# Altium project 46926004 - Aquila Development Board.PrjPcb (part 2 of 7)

## Sheet 210_Translators.SchDoc: Aquila Development Board
size Letter; Organization: Linear Computing Inc.; Address1: 6415 Northwest Drive; Address2: Mississauga, ON, L4V1X1; Address3: Canada; SheetNumber: 8; SheetTotal: 34
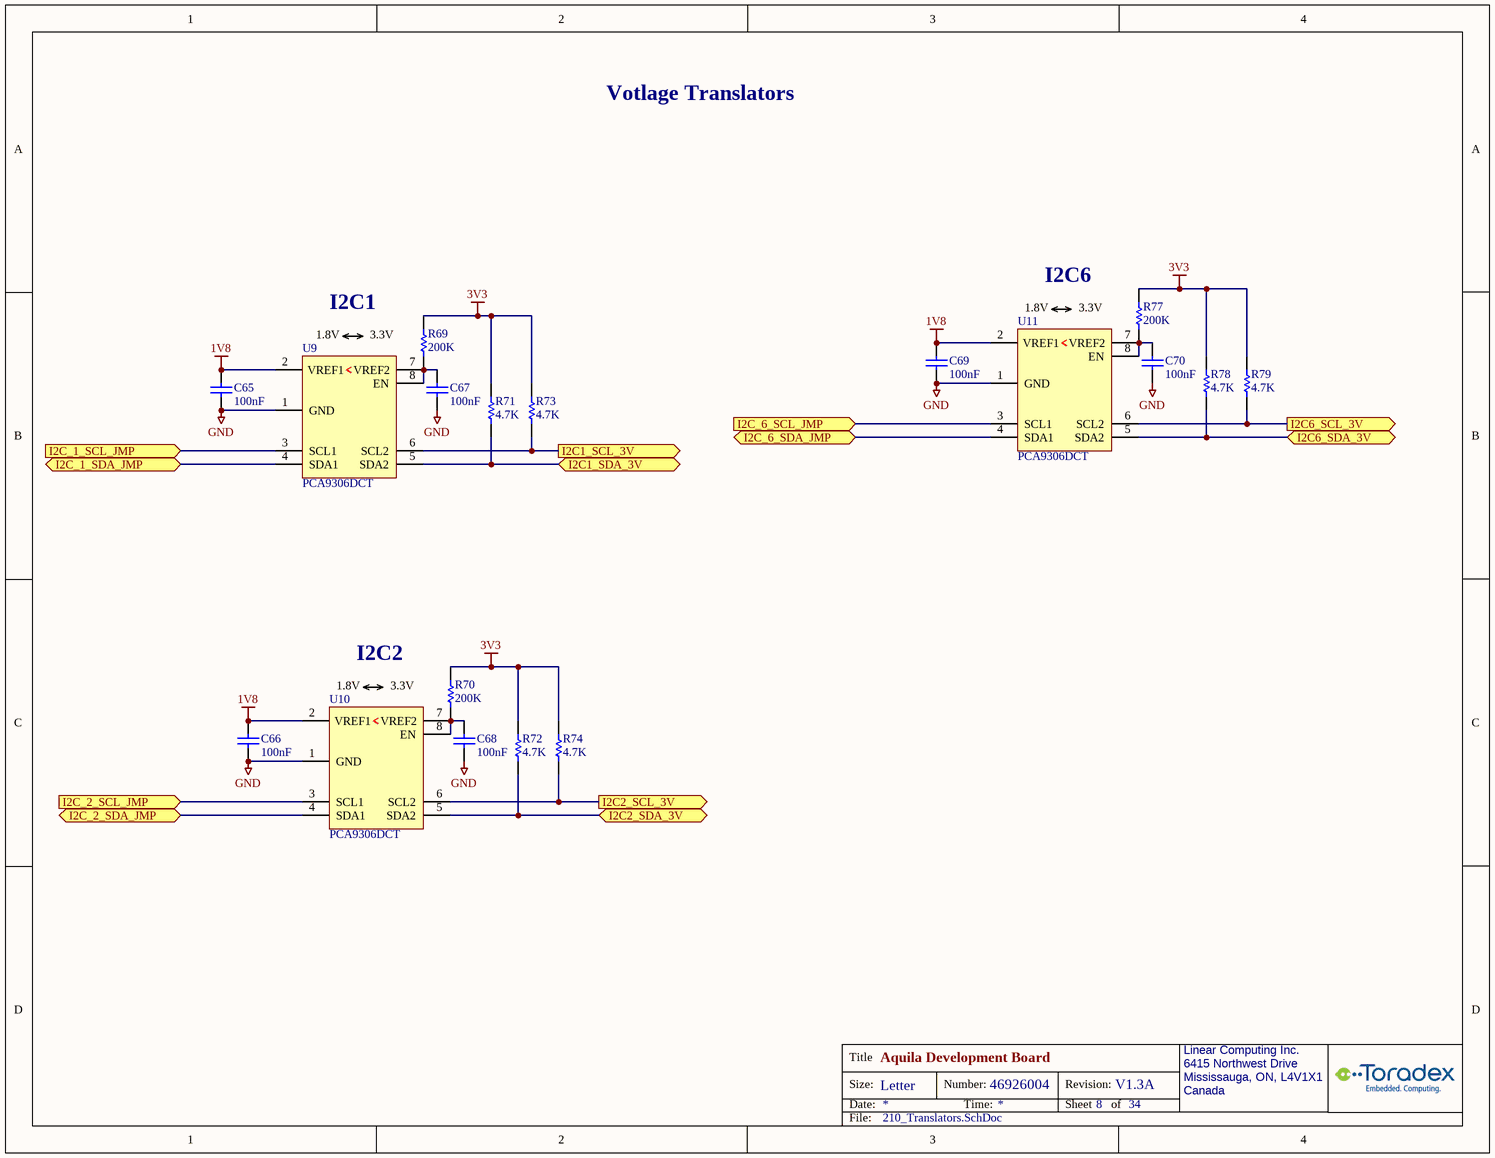
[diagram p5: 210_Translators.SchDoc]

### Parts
C65  100nF  [C0402_CAPC1005L]
C66  100nF  [C0402_CAPC1005L]
C67  100nF  [C0402_CAPC1005L]
C68  100nF  [C0402_CAPC1005L]
C69  100nF  [C0402_CAPC1005L]
C70  100nF  [C0402_CAPC1005L]
R69  value 200K  [R0402_RESC1005L]  (hidden comment: 1540-Res-0402-200k)
R70  value 200K  [R0402_RESC1005L]  (hidden comment: 1540-Res-0402-200k)
R71  value 4.7K  [R0402_RESC1005L]  (hidden comment: 2233-Res-0402-4.7K)
R72  value 4.7K  [R0402_RESC1005L]  (hidden comment: 2233-Res-0402-4.7K)
R73  value 4.7K  [R0402_RESC1005L]  (hidden comment: 2233-Res-0402-4.7K)
R74  value 4.7K  [R0402_RESC1005L]  (hidden comment: 2233-Res-0402-4.7K)
R77  value 200K  [R0402_RESC1005L]  (hidden comment: 1540-Res-0402-200k)
R78  value 4.7K  [R0402_RESC1005L]  (hidden comment: 2233-Res-0402-4.7K)
R79  value 4.7K  [R0402_RESC1005L]  (hidden comment: 2233-Res-0402-4.7K)
U9  PCA9306DCT  [TSSO3x5-G8/X.35]
U10  PCA9306DCT  [TSSO3x5-G8/X.35]
U11  PCA9306DCT  [TSSO3x5-G8/X.35]

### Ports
I2C1_SCL_3V (out), I2C1_SDA_3V (bidir), I2C2_SCL_3V (out), I2C2_SDA_3V (bidir), I2C6_SCL_3V (out), I2C6_SDA_3V (bidir), I2C_1_SCL_JMP (in), I2C_1_SDA_JMP (bidir), I2C_2_SCL_JMP (in), I2C_2_SDA_JMP (bidir), I2C_6_SCL_JMP (in), I2C_6_SDA_JMP (bidir)

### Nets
1V8: C65.2 C66.2 C69.2 U9.2(VREF1) U10.2(VREF1) U11.2(VREF1)
3V3: R69.1 R70.1 R71.1 R72.1 R73.1 R74.1 R77.1 R78.1 R79.1
GND: C65.1 C66.1 C67.1 C68.1 C69.1 C70.1 U9.1(GND) U10.1(GND) U11.1(GND)
I2C1_SCL_3V: R73.2 U9.6(SCL2) ; port I2C1_SCL_3V
I2C1_SDA_3V: R71.2 U9.5(SDA2) ; port I2C1_SDA_3V
I2C2_SCL_3V: R74.2 U10.6(SCL2) ; port I2C2_SCL_3V
I2C2_SDA_3V: R72.2 U10.5(SDA2) ; port I2C2_SDA_3V
I2C6_SCL_3V: R79.2 U11.6(SCL2) ; port I2C6_SCL_3V
I2C6_SDA_3V: R78.2 U11.5(SDA2) ; port I2C6_SDA_3V
I2C_1_SCL_JMP: U9.3(SCL1) ; port I2C_1_SCL_JMP
I2C_1_SDA_JMP: U9.4(SDA1) ; port I2C_1_SDA_JMP
I2C_2_SCL_JMP: U10.3(SCL1) ; port I2C_2_SCL_JMP
I2C_2_SDA_JMP: U10.4(SDA1) ; port I2C_2_SDA_JMP
I2C_6_SCL_JMP: U11.3(SCL1) ; port I2C_6_SCL_JMP
I2C_6_SDA_JMP: U11.4(SDA1) ; port I2C_6_SDA_JMP
NetC67_2: C67.2 R69.2 U9.7(VREF2) U9.8(EN)
NetC68_2: C68.2 R70.2 U10.7(VREF2) U10.8(EN)
NetC70_2: C70.2 R77.2 U11.7(VREF2) U11.8(EN)

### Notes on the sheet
- Votlage Translators
- I2C6
- (near U9) 1.8V
- I2C1
- 3.3V
- (near U11) 1.8V
- (near U10) 1.8V
- I2C2

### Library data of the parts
C65-C70 = 1566-Cap-0402-100nF/50V: (-55 to 125 DegC AEC) Cap Ceramic 0.1uF 50V X7R 10% 0402; MfrNo: GRT155R71H104KE01D; Mfr: Murata; Alt: CL05B104KB54PNC,GCM155R71H104ME02D,GCM155R71H104KE02D,GCM155R71H104KE02J; PN: 1566
R69 R70 R77 = 1540-Res-0402-200k: (-55 to 155 DegC AEC) RES 200K OHM 1% 1/16W 100ppm 0402; Mfr: Stackpole Electronics; MfrNo: RMCF0402FT200K; Alt: AC0402FR-07200KL,AC0402FR-7W200KL,ERJ-2RKF2003X; PN: 1540
R71-R74 R78 R79 = 2233-Res-0402-4.7K: (-55 to 155 DegC) RES 4.70K OHM 1/16W 1% 0402 100ppm; MfrNo: RC0402FR-074K7L; Mfr: Yageo; PN: 2233
U9-U11 = 0972-PCA9306DCT: (-40 to 85 DegC) IC TRANSLTR BIDIRECTIONAL I2C SM8; MfrNo: PCA9306DCTR; Mfr: Texas Instruments; PN: 972

## Sheet 220_Debug.SchDoc: Aquila Development Board
size Letter; Organization: Toradex Solutions Inc.; Address1: 6415 Northwest Drive; Address2: Mississauga, ON, L4V 1X1; Address3: Canada; SheetNumber: 10; SheetTotal: 34
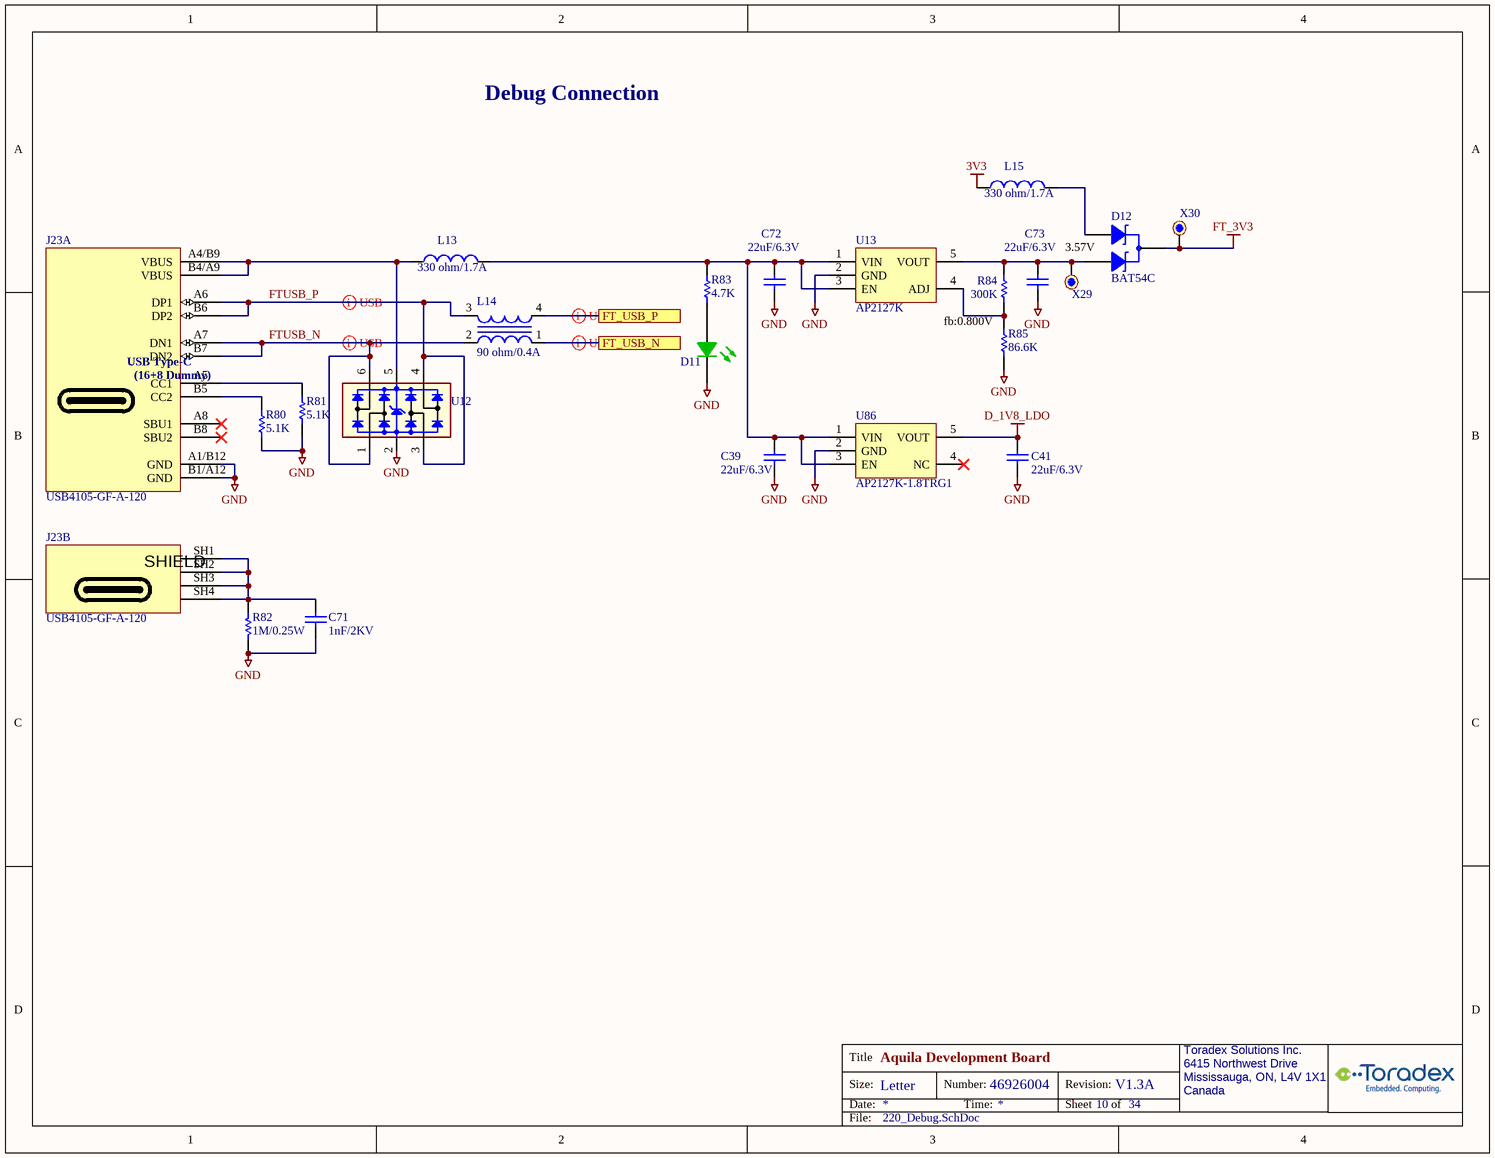
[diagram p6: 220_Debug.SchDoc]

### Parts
C39  22uF/6.3V  [C0402_CAPC1005L]
C41  22uF/6.3V  [C0402_CAPC1005L]
C71  value 1nF/2KV  [C/1206]  (hidden comment: 0567-Cap-1206-1nF/2KV)
C72  22uF/6.3V  [C0402_CAPC1005L]
C73  22uF/6.3V  [C0402_CAPC1005L]
D11  Status  [LED-SMT-0603_APT1608CGCK]  (value not drawn)
D12  BAT54C  [SOT23_M]
J23  USB4105-GF-A-120  [GCT_USB4105GFA120]  (parts A,B of 2)
L13  value 330 ohm/1.7A  [C/0603]  (hidden comment: 0405-Fer-0603-330ohm/1.7A)
L14  90 ohm/0.4A  [COMMON_CHOKE_BOURNS_SRF2012-900YA]
L15  value 330 ohm/1.7A  [C/0603]  (hidden comment: 0405-Fer-0603-330ohm/1.7A)
R80  value 5.1K  [R/0603]  (hidden comment: 0227-Res-0603-5.1K)
R81  value 5.1K  [R/0603]  (hidden comment: 0227-Res-0603-5.1K)
R82  value 1M/0.25W  [R/1206]  (hidden comment: 1860-Res-1206-1M-5%-0.25W)
R83  value 4.7K  [R0402_RESC1005L]  (hidden comment: 2233-Res-0402-4.7K)
R84  value 300K  [R/0603]  (hidden comment: 0176-Res-0603-300K)
R85  value 86.6K  [R0402_RESC1005L]  (hidden comment: 1539-Res-0402-86.6k)
U12  TPD4E001  [SOT23-6]  (value not drawn)
U13  AP2127K  [SOT23-5AN]
U86  AP2127K-1.8TRG1  [SOT23-5AN]
X29  000-TestPoint  [TestPoint_1]  (value not drawn)
X30  000-TestPoint  [TestPoint_1]  (value not drawn)

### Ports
FT_USB_N, FT_USB_P

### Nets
3V3: L15.1
D_1V8_LDO: C41.1 U86.5(VOUT)
FT_3V3: D12.3(K) X30.1
GND: C39.2 C41.2 C71.1 C72.2 C73.2 D11.2(K) J23.A1/B12(GND) J23.B1/A12(GND) R80.2 R81.2 R82.2 R85.1 U12.2 U13.2(GND) U86.2(GND)
FT_USB_N: L14.1 ; port FT_USB_N
FT_USB_P: L14.4 ; port FT_USB_P
FTUSB_N: J23.A7(DN1) J23.B7(DN2) L14.2 U12.1 U12.6
FTUSB_P: J23.A6(DP1) J23.B6(DP2) L14.3 U12.3 U12.4
NetC39_1: C39.1 C72.1 L13.2 R83.2 U13.1(VIN) U13.3(EN) U86.1(VIN) U86.3(EN)
NetC71_2: C71.2 J23.SH1(SHIELD) J23.SH2(SHIELD) J23.SH3(SHIELD) J23.SH4(SHIELD) R82.1
NetC73_1: C73.1 D12.2(A2) R84.1 U13.5(VOUT) X29.1
NetD11_1: D11.1(A) R83.1
NetD12_1: D12.1(A1) L15.2
NetJ23_A4/B9: J23.A4/B9(VBUS) J23.B4/A9(VBUS) L13.1 U12.5
NetJ23_A5: J23.A5(CC1) R81.1
NetJ23_B5: J23.B5(CC2) R80.1
NetR84_2: R84.2 R85.2 U13.4(ADJ)

Not connected (* = marked no-connect by the designer): J23 A8(SBU1)* B8(SBU2)*; U86 4(NC)*

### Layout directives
differential pair; differential pair class USB_FT: FT_USB_N, FT_USB_P
differential pair; differential pair class USB_FT_CON: FTUSB_N, FTUSB_P

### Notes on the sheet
- Debug Connection
- 3.57V
- (near R85) fb:0.800V

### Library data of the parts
C39 C41 C72 C73 = 2404-Cap-0402-22uF/6.3V: (-55 to 85 DegC) CAP CER 22UF 6.3V 20% X5R 0402; MfrNo: GRM155R60J226ME11D; Mfr: Murata; PN: 2404
C71 = 0567-Cap-1206-1nF/2KV: (-55 to 125 DegC) CAP CER 1000PF 2KV X7R 1206; Mfr: Johanson Dielectrics Inc.; MfrNo: 202R18W102KV4E; PN: 567; Alt: 478-2956-1-ND; Alt2: 399-4819-1-ND
D11 = 0333-LED Green 0603: (-40 to 85 DegC) LED GREEN 0603 50mcd; MfrNo: APT1608CGCK; Mfr: Kingbright; Alt: 754-1357-1-ND; Alt2: 160-1834-1-ND; PN: 333; DR: 754-1116-6-ND; DR2: 604-APT1608CGCK
D12 = 0242B-BAT54C: (-55 to 125 DegC) DIODE SCHOTTKY 30V 200MA SOT23, comm. Cathode; Mfr: ON Semi; MfrNo: BAT54CLT1G; Alt: BAT54CFSCT-ND; Alt2: BAT54C-FDICT-ND; PN: 242; TR: BAT54CLT1GOSTR-ND; DR: BAT54CLT1GOSDKR-ND; DR2: 863-BAT54CLT1G
J23 = 1660-Conn-USB-Type-C: (-40 to 85 DegC) Conn USB TYPE C RA, 24 (16+8 Dummy) Position, SMT/TH; Mfr: Global Connector Technology; Desc: (-40 to 85 DegC) Conn USB TYPE C RA SMT/TH; PN: 1660
L13 L15 = 0405-Fer-0603-330ohm/1.7A: (-55 to 125 DegC) FERRITE BEAD 330 OHM 0603 1.7A 80mohm, typ 48mohm; Mfr: TDK Corporation; MfrNo: MPZ1608S331ATA00; PN: 405; TR: 445-5221-2-ND; DR: 445-5221-6-ND; DR2: 810-MPZ1608S331ATA00
L14 = 0277-Ind-2x1.2-90ohm/0.4A-Choke: (-40 to 125 DegC) INDUCTOR COMMON MODE 90 OHM 0.4A 0.3ohm; MfrNo: SRF2012-900YA; Mfr: Bourns Inc.; PN: 277; Alt: 445-2207-1-ND
R80 R81 = 0227-Res-0603-5.1K: (-55 to 155 DegC) RES 5.1K OHM 1/10W 1% 0603 SMD; Mfr: Rohm; MfrNo: MCR03ERTF5101; Alt: 1276-4713-1-ND; Alt2: 311-5.10KHRCT-ND; PN: 227
R82 = 1860-Res-1206-1M-5%-0.25W: (-55 to 155 DegC) RES SMD 1M OHM 5% 0.25W 10ppm 1206; Mfr: TE Connectivity; MfrNo: CRGCQ1206J1M0; PN: 1860; Alt: RMCF1206JT1M00, RMCF1206JG1M00, CR1206-JW-105ELF
R83 = 2233-Res-0402-4.7K: as R71-R74 on sheet 210_Translators
R84 = 0176-Res-0603-300K: (-55 to 155 DegC) RES 300K OHM 1/10W 1% 0603 SMD; Mfr: Yageo; MfrNo: RC0603FR-07300KL; Alt: RHM300KCFCT-ND; PN: 176; Alt2: P300KHCT-ND; TR: 311-300KHRTR-ND
R85 = 1539-Res-0402-86.6k: (-55 to 155 DegC AEC) RES 86.6K OHM 1% 1/16W 100ppm 0402; Mfr: Stackpole Electronics; MfrNo: RMCF0402FT86K6; Alt: AC0402FR-0786K6L,RK73H1ETTP8662F,ERJ-2RKF8662X; PN: 1539
U12 = 0740-TPD4E001: (-40 to 125 DegC AEC) TVS DIODE 5.5VWM 16VC SOT-23-6; MfrNo: TPD4E001QDBVRQ1; Mfr: Texas Instruments; PN: 740; Alt: TPD4E001DBVR
U13 = 0968-AP2127K: (-40 to 85 DegC) IC REG LIN LDO POS ADJ 300MA (450 max) SOT23-5 2.5-6 Vin 0.3Vd@0.3A; Mfr: Diodes Incorporated; MfrNo: AP2127K-ADJTRG1; PN: 968
U86 = 2737-AP2127K-1.8TRG1: (-40 to 85 DegC) IC REG LIN LDO POS 1.8V 300MA (450 max) SOT23-5 2.5-6 Vin 0.3Vd@0.3A; Mfr: Diodes; PN: 2737
X29 X30 = 000-TestPoint: TestPoint TH; Note: this is PCB footprint only, no parts to buy or assemble

## Sheet 300_USB1_OTG.SchDoc: Aquila Development Board
size A3; Organization: Toradex Solutions Inc.; Address1: 6415 Northwest Drive; Address2: Mississauga, ON, L4V 1X1; Address3: Canada; SheetNumber: 14; SheetTotal: 34
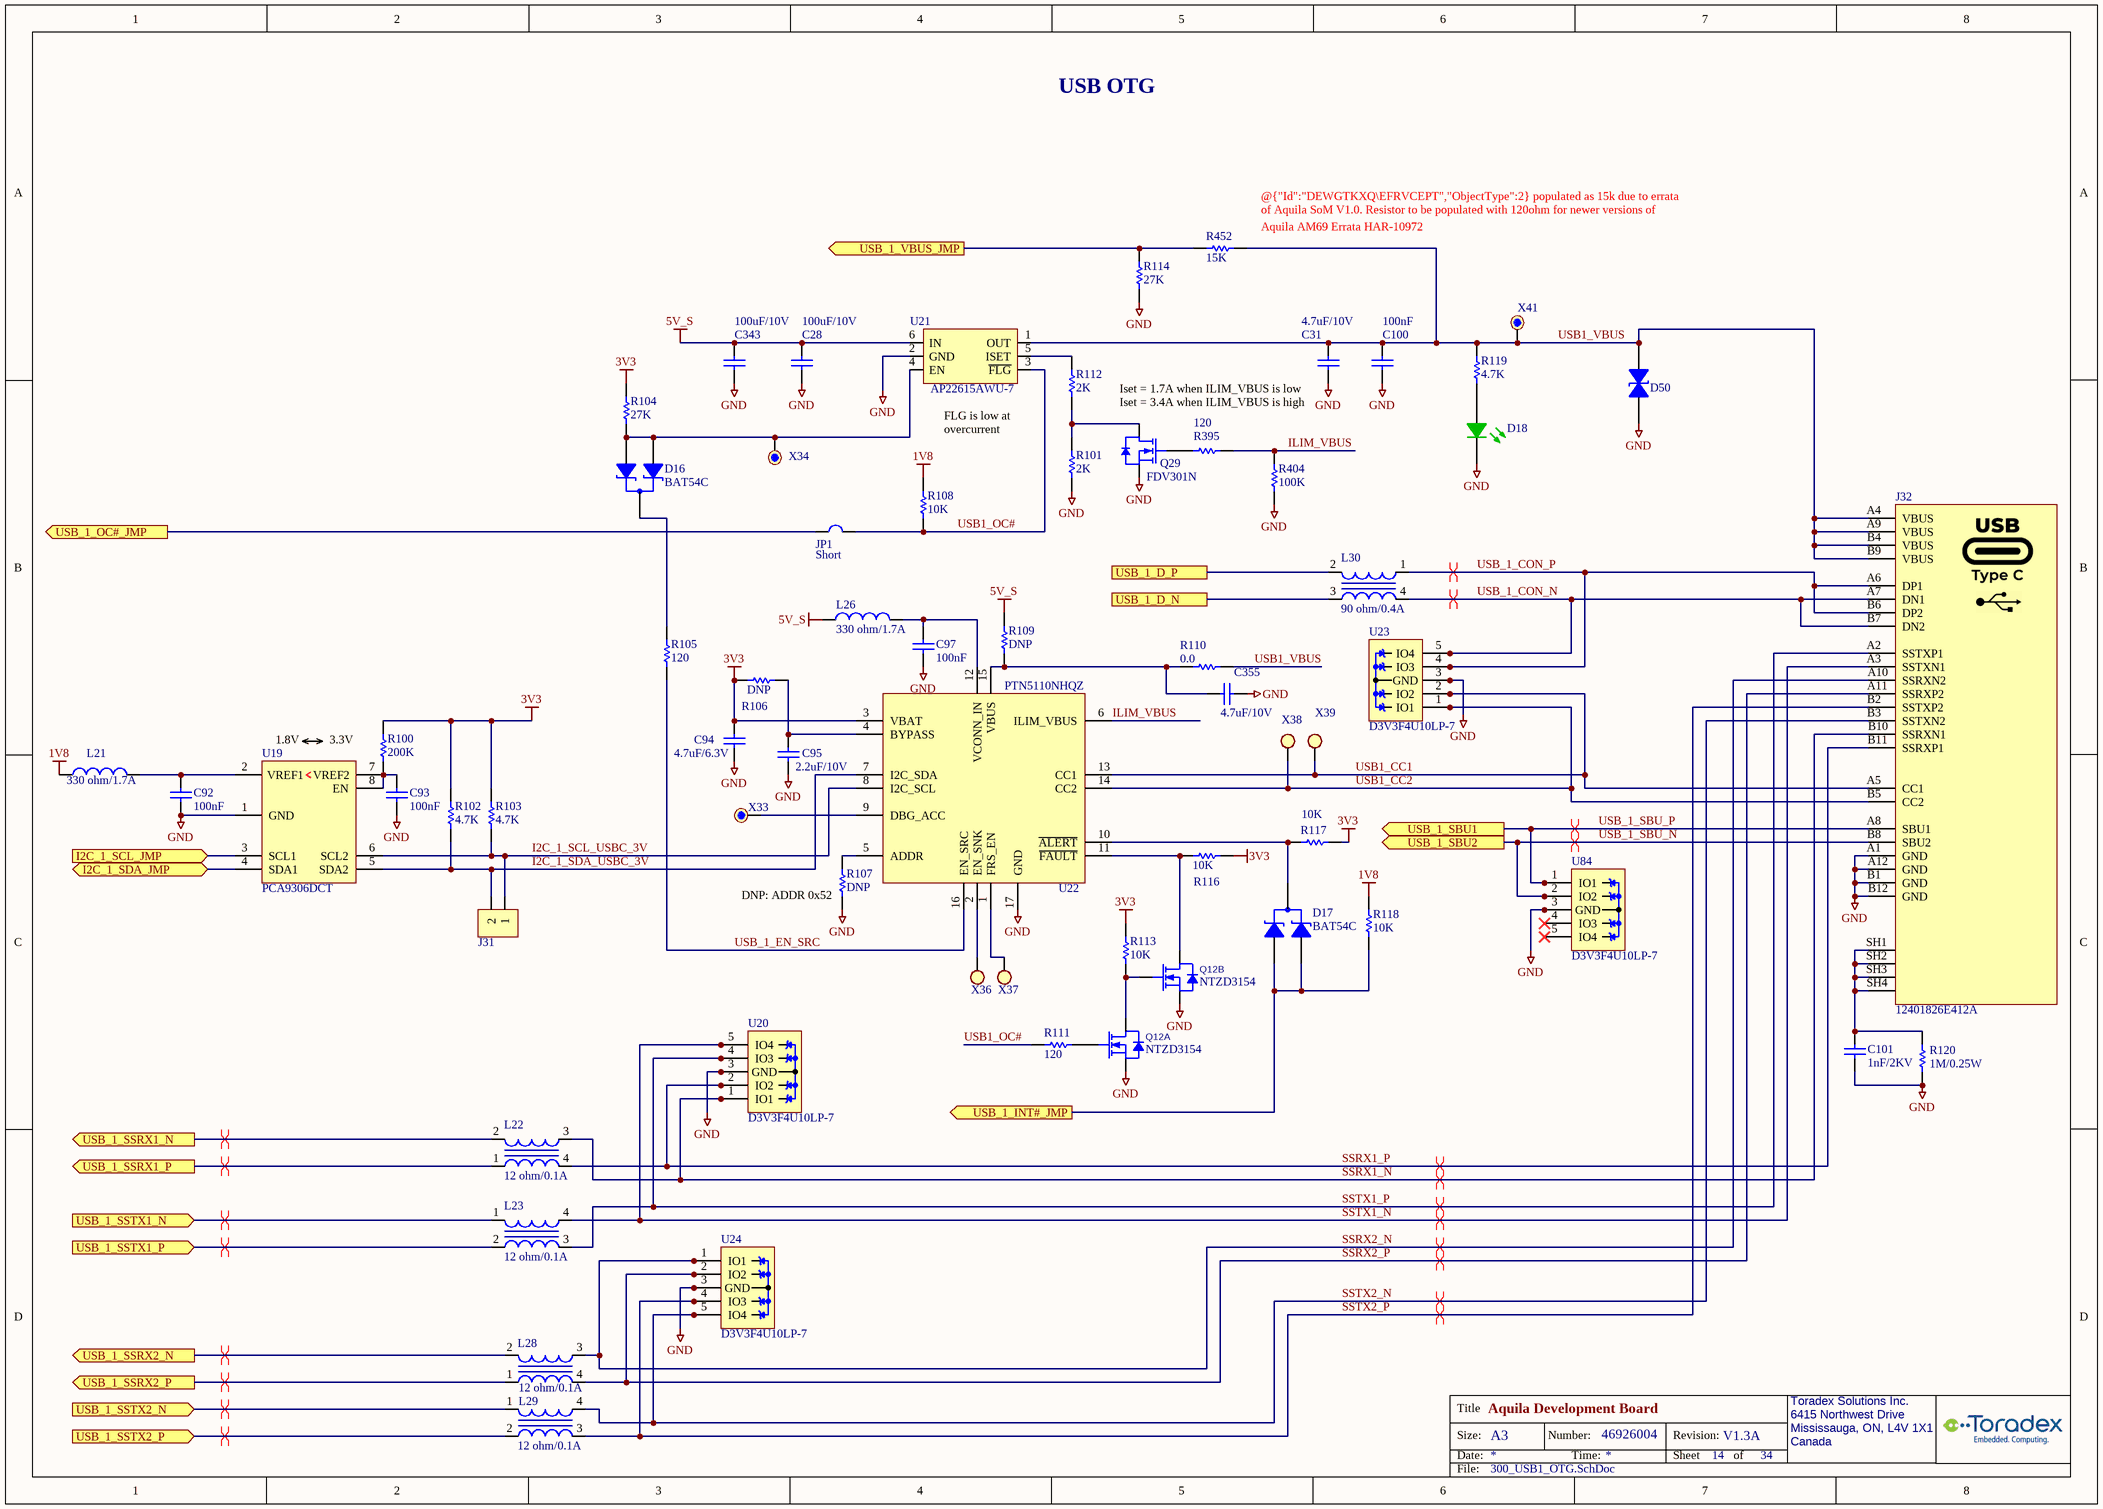
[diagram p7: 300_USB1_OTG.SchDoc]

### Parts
C28  100uF/10V  [C/1206]
C31  value 4.7uF/10V  [C/0603]  (hidden comment: 2093-Cap-0603-4.7uF/10V)
C92  100nF  [C0402_CAPC1005L]
C93  100nF  [C0402_CAPC1005L]
C94  value 4.7uF/6.3V  [C0402_CAPC1005L]  (hidden comment: 0354-Cap-0402-4.7uF/6.3V)
C95  value 2.2uF/10V  [C0402_CAPC1005L]  (hidden comment: 2234-Cap-0402-2.2uF/10V)
C97  100nF  [C0402_CAPC1005L]
C100  100nF  [C0402_CAPC1005L]
C101  value 1nF/2KV  [C/1206]  (hidden comment: 0567-Cap-1206-1nF/2KV)
C343  100uF/10V  [C/1206]
C355  value 4.7uF/10V  [C/0603]  (hidden comment: 2093-Cap-0603-4.7uF/10V)
D16  BAT54C  [SOT23_M]
D17  BAT54C  [SOT23_M]
D18  Status  [LED-SMT-0603_APT1608CGCK]  (value not drawn)
D50  D5V0L1B2S9-7  [SOD923_DIO]  (value not drawn)
J31  000-Hdr-2pin  [HDR1X2]  (value not drawn)  (no BOM)
J32  12401826E412A  [AMPHENOL_12401826E412A]
JP1  Short  [Short_040]  (net tie, no BOM)
L21  value 330 ohm/1.7A  [C/0603]  (hidden comment: 0405-Fer-0603-330ohm/1.7A)
L22  12 ohm/0.1A  [COIL0302]
L23  12 ohm/0.1A  [COIL0302]
L26  value 330 ohm/1.7A  [C/0603]  (hidden comment: 0405-Fer-0603-330ohm/1.7A)
L28  12 ohm/0.1A  [COIL0302]
L29  12 ohm/0.1A  [COIL0302]
L30  90 ohm/0.4A  [COMMON_CHOKE_BOURNS_SRF2012-900YA]
Q12  NTZD3154  [SOT563]  (parts A,B of 2)
Q29  FDV301N  [SOT23]
R100  value 200K  [R0402_RESC1005L]  (hidden comment: 1540-Res-0402-200k)
R101  value 2K  [R/0603]  (hidden comment: 1758-Res-0603-2K)
R102  value 4.7K  [R0402_RESC1005L]  (hidden comment: 2233-Res-0402-4.7K)
R103  value 4.7K  [R0402_RESC1005L]  (hidden comment: 2233-Res-0402-4.7K)
R104  value 27K  [R0402_RESC1005L]  (hidden comment: 1538-Res-0402-27k)
R105  value 120  [R0402_RESC1005L]  (hidden comment: 1552-Res-0402-120)
R106  value DNP  [R/0603]  (hidden comment: 0000-Res-0603-DNP)
R107  value DNP  [R/0603]  (hidden comment: 0000-Res-0603-DNP)
R108  value 10K  [R0402_RESC1005L]  (hidden comment: 1572-Res-0402-10K)
R109  value DNP  [R/0603]  (hidden comment: 0000-Res-0603-DNP)
R110  value 0.0  [R/0603]  (hidden comment: 0195-Res-0603-0.0ohm)
R111  value 120  [R0402_RESC1005L]  (hidden comment: 1552-Res-0402-120)
R112  value 2K  [R/0603]  (hidden comment: 1758-Res-0603-2K)
R113  value 10K  [R0402_RESC1005L]  (hidden comment: 1572-Res-0402-10K)
R114  value 27K  [R0402_RESC1005L]  (hidden comment: 1538-Res-0402-27k)
R116  value 10K  [R0402_RESC1005L]  (hidden comment: 1572-Res-0402-10K)
R117  value 10K  [R0402_RESC1005L]  (hidden comment: 1572-Res-0402-10K)
R118  value 10K  [R0402_RESC1005L]  (hidden comment: 1572-Res-0402-10K)
R119  value 4.7K  [R0402_RESC1005L]  (hidden comment: 2233-Res-0402-4.7K)
R120  value 1M/0.25W  [R/1206]  (hidden comment: 1860-Res-1206-1M-5%-0.25W)
R395  value 120  [R0402_RESC1005L]  (hidden comment: 1552-Res-0402-120)
R404  value 100K  [R0402_RESC1005L]  (hidden comment: 1977-Res-0402-100K)
R452  value 15K  [R0402_RESC1005L]  (hidden comment: 1550-Res-0402-15K)
U19  PCA9306DCT  [TSSO3x5-G8/X.35]
U20  D3V3F4U10LP-7  [10-UFDFN]
U21  AP22615AWU-7  [TSOT26]
U22  PTN5110NHQZ  [QFN40P260X260X40-17N-D]
U23  D3V3F4U10LP-7  [10-UFDFN]
U24  D3V3F4U10LP-7  [10-UFDFN]
U84  D3V3F4U10LP-7  [10-UFDFN]
X33  000-TestPoint  [TestPoint_1]  (value not drawn)
X34  000-TestPoint  [TestPoint_1]  (value not drawn)
X36  000-TestPoint2  [TestPoint_3]  (value not drawn)
X37  000-TestPoint2  [TestPoint_3]  (value not drawn)
X38  000-TestPoint2  [TestPoint_3]  (value not drawn)
X39  000-TestPoint2  [TestPoint_3]  (value not drawn)
X41  000-TestPoint  [TestPoint_1]  (value not drawn)

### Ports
I2C_1_SCL_JMP (in), I2C_1_SDA_JMP (bidir), USB_1_D_N, USB_1_D_P, USB_1_INT#_JMP (out), USB_1_OC#_JMP (out), USB_1_SBU1 (out), USB_1_SBU2 (out), USB_1_SSRX1_N (out), USB_1_SSRX1_P (out), USB_1_SSRX2_N (out), USB_1_SSRX2_P (out), USB_1_SSTX1_N (in), USB_1_SSTX1_P (in), USB_1_SSTX2_N (in), USB_1_SSTX2_P (in), USB_1_VBUS_JMP (out)

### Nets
1V8: L21.1 R108.1 R118.1
3V3: C94.2 R100.1 R102.1 R103.1 R104.2 R106.1 R113.1 R116.1 R117.1 U22.3(VBAT)
5V_S: C28.2 C343.2 L26.1 R109.2 U21.6(IN)
GND: C28.1 C31.1 C92.1 C93.1 C94.1 C95.1 C97.1 C100.1 C101.1 C343.1 C355.1 D18.2(K) D50.1 J32.A1(GND) J32.A12(GND) J32.B1(GND) J32.B12(GND) Q12.1(S) Q12.4(S) Q29.2(S) R101.2 R107.1 R114.1 R120.2 R404.1 U19.1(GND) U20.3(GND) U20.8(GND) U21.2(GND) U22.17(GND) U23.3(GND) U23.8(GND) U24.3(GND) U24.8(GND) U84.3(GND) U84.8(GND)
I2C_1_SCL_JMP: U19.3(SCL1) ; port I2C_1_SCL_JMP
I2C_1_SCL_USBC_3V: J31.1 R103.2 U19.6(SCL2) U22.8(I2C_SCL)
I2C_1_SDA_JMP: U19.4(SDA1) ; port I2C_1_SDA_JMP
I2C_1_SDA_USBC_3V: J31.2 R102.2 U19.5(SDA2) U22.7(I2C_SDA)
ILIM_VBUS: R395.1 R404.2 U22.6(ILIM_VBUS)
SSRX1_N: J32.B10(SSRXN1) L22.3 U20.1(IO1) U20.10(NC)
SSRX1_P: J32.B11(SSRXP1) L22.4 U20.2(IO2) U20.9(NC)
SSRX2_N: J32.A10(SSRXN2) L28.3 U24.1(IO1) U24.10(NC)
SSRX2_P: J32.A11(SSRXP2) L28.4 U24.2(IO2) U24.9(NC)
SSTX1_N: J32.A3(SSTXN1) L23.4 U20.5(IO4) U20.6(NC)
SSTX1_P: J32.A2(SSTXP1) L23.3 U20.4(IO3) U20.7(NC)
SSTX2_N: J32.B3(SSTXN2) L29.4 U24.5(IO4) U24.6(NC)
SSTX2_P: J32.B2(SSTXP2) L29.3 U24.4(IO3) U24.7(NC)
USB1_CC1: J32.A5(CC1) U22.13(CC1) U23.2(IO2) U23.9(NC) X39.1
USB1_CC2: J32.B5(CC2) U22.14(CC2) U23.1(IO1) U23.10(NC) X38.1
USB1_OC#: JP1.2(C2) R108.2 R111.2 U21.3(~{FLG})
USB1_VBUS: C31.2 C100.2 D50.2 J32.A4(VBUS) J32.A9(VBUS) J32.B4(VBUS) J32.B9(VBUS) R110.2 R119.2 R452.1 U21.1(OUT) X41.1
USB_1_CON_N: J32.A7(DN1) J32.B7(DN2) L30.4 U23.5(IO4) U23.6(NC)
USB_1_CON_P: J32.A6(DP1) J32.B6(DP2) L30.1 U23.4(IO3) U23.7(NC)
USB_1_D_N: L30.3 ; port USB_1_D_N
USB_1_D_P: L30.2 ; port USB_1_D_P
USB_1_EN_SRC: R105.2 U22.16(EN_SRC)
USB_1_INT#_JMP: D17.1(A1) D17.2(A2) R118.2 ; port USB_1_INT#_JMP
USB_1_OC#_JMP: JP1.1(C1) ; port USB_1_OC#_JMP
USB_1_SBU_N: J32.B8(SBU2) U84.2(IO2) U84.9(NC) ; port USB_1_SBU2
USB_1_SBU_P: J32.A8(SBU1) U84.1(IO1) U84.10(NC) ; port USB_1_SBU1
USB_1_SSRX1_N: L22.2 ; port USB_1_SSRX1_N
USB_1_SSRX1_P: L22.1 ; port USB_1_SSRX1_P
USB_1_SSRX2_N: L28.2 ; port USB_1_SSRX2_N
USB_1_SSRX2_P: L28.1 ; port USB_1_SSRX2_P
USB_1_SSTX1_N: L23.1 ; port USB_1_SSTX1_N
USB_1_SSTX1_P: L23.2 ; port USB_1_SSTX1_P
USB_1_SSTX2_N: L29.1 ; port USB_1_SSTX2_N
USB_1_SSTX2_P: L29.2 ; port USB_1_SSTX2_P
USB_1_VBUS_JMP: R114.2 R452.2 ; port USB_1_VBUS_JMP
NetC92_2: C92.2 L21.2 U19.2(VREF1)
NetC93_2: C93.2 R100.2 U19.7(VREF2) U19.8(EN)
NetC95_2: C95.2 R106.2 U22.4(BYPASS)
NetC97_2: C97.2 L26.2 U22.12(VCONN_IN)
NetC101_2: C101.2 J32.SH1(SHIELD) J32.SH2(SHIELD) J32.SH3(SHIELD) J32.SH4(SHIELD) R120.1
NetC355_2: C355.2 R109.1 R110.1 U22.15(VBUS)
NetD16_1: D16.1(A1) D16.2(A2) R104.1 U21.4(EN) X34.1
NetD16_3: D16.3(K) R105.1
NetD17_3: D17.3(K) R117.2 U22.10(~{ALERT})
NetD18_1: D18.1(A) R119.1
NetQ12_2: Q12.2(G) R111.1
NetQ12_3: Q12.3(D) R116.2 U22.11(~{FAULT})
NetQ12_5: Q12.5(G) Q12.6(D) R113.2
NetQ29_1: Q29.1(G) R395.2
NetQ29_3: Q29.3(D) R101.1 R112.2
NetR107_2: R107.2 U22.5(ADDR)
NetR112_1: R112.1 U21.5(ISET)
NetU22_1: U22.1(FRS_EN) X37.1
NetU22_2: U22.2(EN_SNK) X36.1
NetU22_9: U22.9(DBG_ACC) X33.1
NetU84_4: U84.4(IO3) U84.7(NC)
NetU84_5: U84.5(IO4) U84.6(NC)

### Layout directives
differential pair; differential pair class USB; differential pair class USB_1_CON: USB_1_CON_N, USB_1_CON_P
differential pair; differential pair class USB_1_SSRX1: USB_1_SSRX1_N, USB_1_SSRX1_P
differential pair; differential pair class USB_1_SSTX1: USB_1_SSTX1_N, USB_1_SSTX1_P
differential pair; differential pair class USB_1_SSRX2: USB_1_SSRX2_N, USB_1_SSRX2_P
differential pair; differential pair class USB_1_SSTX2: USB_1_SSTX2_N, USB_1_SSTX2_P
differential pair; differential pair class SSRX1: SSRX1_N, SSRX1_P
differential pair; differential pair class SSTX1: SSTX1_N, SSTX1_P
differential pair; differential pair class SSRX2: SSRX2_N, SSRX2_P
differential pair; differential pair class SSTX2: SSTX2_N, SSTX2_P
differential pair; differential pair class USB_1_SBU; differential pair class USB: USB_1_SBU_N, USB_1_SBU_P

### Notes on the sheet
- USB OTG
- (near R452) @{"Id":"DEWGTKXQ\EFRVCEPT","ObjectType":2} populated as 15k due to errata of Aquila SoM V1.0. Resistor to be populated with 120ohm for newer versions of SoM
- (near R452) Aquila AM69 Errata HAR-10972
- FLG is low at
- overcurrent
- (near C31) Iset = 1.7A when ILIM_VBUS is low
- Iset = 3.4A when ILIM_VBUS is high
- (near U19) 1.8V
- 3.3V
- (near R107) DNP: ADDR 0x52

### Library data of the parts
C28 C343 = 2282-Cap-1206-100uF/10V: (-55 to 85 DegC) CAP CER 100UF 10V 20% X5R 1206; Mfr: Murata; MfrNo: GRM31CR61A107MEA8L; PN: 2282
C31 C355 = 2093-Cap-0603-4.7uF/10V: (-55 to 85 DegC) CAP CER 4.7UF 10V 20% X5R 0603; MfrNo: CL10A475KP8NNNC; Mfr: Samsung; PN: 2093
C92 C93 C97 C100 = 1566-Cap-0402-100nF/50V: as C65-C70 on sheet 210_Translators
C94 = 0354-Cap-0402-4.7uF/6.3V: (-55 to 85 DegC) CAP CER 4.7UF 6.3V 20% X5R 0402; Mfr: Murata Electronics North America; MfrNo: GRM155R60J475ME87D; Alt: 1276-1483-1-ND; Alt2: 490-5915-1-ND; PN: 354
C95 = 2234-Cap-0402-2.2uF/10V: (-55 to 85 DegC) CAP CER 2.2UF 10V 20% X5R 0402; Mfr: Yageo; MfrNo: CC0402MRX5R6BB225; PN: 2234
C101 = 0567-Cap-1206-1nF/2KV: as C71 on sheet 220_Debug
D16 D17 = 0242B-BAT54C: as D12 on sheet 220_Debug
D18 = 0333-LED Green 0603: as D11 on sheet 220_Debug
D50 = 1655-D5V0L1B2S9-7: (-65 to 155 DegC) TVS DIODE Vwm:5V Vcl:14V@6A SOD-923; Mfr: Diodes; PN: 1655
J31 = 000-Hdr-2pin: Header, 2-Pin; Note: PCB footprint only, no parts to buy or assemble
J32 = 1512-Conn-USB-Type-C: (-40 to 85 DegC) Conn USB TYPE C RA SMT; Mfr: Amphenol Communications Solutions; PN: 1512
JP1 = 000-Jumper-Short: Jumper Wire
L21 L26 = 0405-Fer-0603-330ohm/1.7A: as L13 on sheet 220_Debug
L22 L23 L28 L29 = 1371-Ind-0.8x0.6-12ohm/0.1A-Choke: (-40 to 85 DegC) Ind CMC Choke 12 Ohm 0.1A 1ohm 0.85x0.65x0.5mm; MfrNo: EXC-14CH120U; Mfr: Panasonic; PN: 1371
L30 = 0277-Ind-2x1.2-90ohm/0.4A-Choke: as L14 on sheet 220_Debug
Q12 = 1146-NTZD3154NT1G: (-55 to 150 DegC) MOSFET 2N-CH (dual) 20V 0.54A SOT-563 1.6x1.6mm Vth:1V Ron typ:400m@4.5V, 500m@2.5V, 700m@1.8V; Mfr: ON Semiconductor; PN: 1146; Alt: NTZD3154NT5G,PMDT290UNE,115
Q29 = 0761-FDV301N: (-55 to 155 DegC) MOSFET N-CH 25V 220MA SOT-23 Vth:1.1V Ron typ:4ohm@3V Vgsm:8V; Mfr: Fairchild/ON Semiconductor; PN: 761; DR: FDV301NDKR-ND; TR: FDV301NTR-ND; Alt: DMN62D0U-13, DMN62D0U-7, DMN61D9U-7
R100 = 1540-Res-0402-200k: as R69 on sheet 210_Translators
R101 R112 = 1758-Res-0603-2K: (-55 to 155 DegC) RES SMD 2K OHM 1% 1/10W 0603 100ppm; Mfr: Yageo; MfrNo: RC0603FR-072KL; PN: 1758
R102 R103 R119 = 2233-Res-0402-4.7K: as R71-R74 on sheet 210_Translators
R104 R114 = 1538-Res-0402-27k: (-55 to 155 DegC AEC) RES 27K OHM 1% 1/16W 100ppm 0402; Mfr: Stackpole Electronics; MfrNo: RMCF0402FT27K0; PN: 1538; Alt: AC0402FR-0727KL,CRGCQ0402F27K
R105 R111 R395 = 1552-Res-0402-120: (-55 to 155 DegC AEC) RES 120 OHM 1% 1/16W 100ppm 0402; Mfr: Stackpole Electronics; MfrNo: RMCF0402FT120R; PN: 1552; Alt: AC0402FR-07120RL,CRGCQ0402F120R
R106 R107 R109 = 0000-Res-0603-DNP: RES 0603
R108 = 1572-Res-0402-10K: (-55 to 155 DegC AEC) RES 10K OHM 1% 1/16W 100ppm 0402; Mfr: Stackpole Electronics; MfrNo: RMCF0402FT10K0; PN: 1572; Alt: AC0402FR-0710KL,AC0402FR-1310KL,CRGCQ0402F10K
R110 = 0195-Res-0603-0.0ohm: (-55 to 155 DegC) RES 0.0 OHM 1/10W JUMP 0603; Mfr: Samsung; MfrNo: RC1608J000CS; Alt: 311-0.0GRCT-ND; Alt2: A106051CT-ND; PN: 195; TR: 1276-3510-2-ND
R113 R116-R118 = 1572-Res-0402-10K: (-55 to 155 DegC AEC) RES 10K OHM 1% 1/16W 100ppm 0402; Mfr: Stackpole Electronics; MfrNo: RMCF0402FT10K0; Alt: AC0402FR-0710KL,AC0402FR-1310KL,CRGCQ0402F10K; PN: 1572
R120 = 1860-Res-1206-1M-5%-0.25W: as R82 on sheet 220_Debug
R404 = 1977-Res-0402-100K: (-55 to 155 DegC) RES 100K OHM 1/16W 1% 0402 SMD; Mfr: Yageo; MfrNo: RC0402FR-07100KL; PN: 1977
R452 = 1550-Res-0402-15K: (-55 to 155 DegC AEC) RES 15K OHM 1% 1/16W 100ppm 0402; Mfr: Stackpole Electronics; MfrNo: RMCF0402FT15K0; Alt: AC0402FR-0715KL,CRGCQ0402F15K; PN: 1550
U19 = 0972-PCA9306DCT: as U9 on sheet 210_Translators
U20 U23 U24 U84 = 1463-D3V3F4U10LP: (-55 to 150 DegC) IC TVS DIODE 4ch Vrm:3.3V Vbr:6.2 Vcl:5V@16A 12KV/12KV 0.5pF 10-UFDFN 0.5mm; Mfr: Diodes; PN: 1463; Notes: Similar: PN1317
U21 = 2238-AP22615AWU-7: (-40 to 85 DegC) IC PWR SWITCH 3-5.5V EN-Active-High ENth:1.2V With-Discharge 40mohm typ ADJ 0.4-4A TSOT-26; Mfr: Diodes; PN: 2238
U22 = 1831-PTN5110: (-40 to 85 DegC) IC USB Type-C CC Logic and port control DRP 16-HX2QFN 2.6x2.6; Mfr: NXP Semiconductors; PN: 1831
X33 X34 X41 = 000-TestPoint: as X29 on sheet 220_Debug
X36-X39 = 000-TestPoint2: TestPoint SMD; Note: PCB footprint only, no parts to buy or assemble

## Sheet 310_USB3.SchDoc: Aquila Development Board
size Letter; Organization: Toradex Solutions Inc.; Address1: 6415 Northwest Drive; Address2: Mississauga, ON, L4V 1X1; Address3: Canada; SheetNumber: 16; SheetTotal: 34
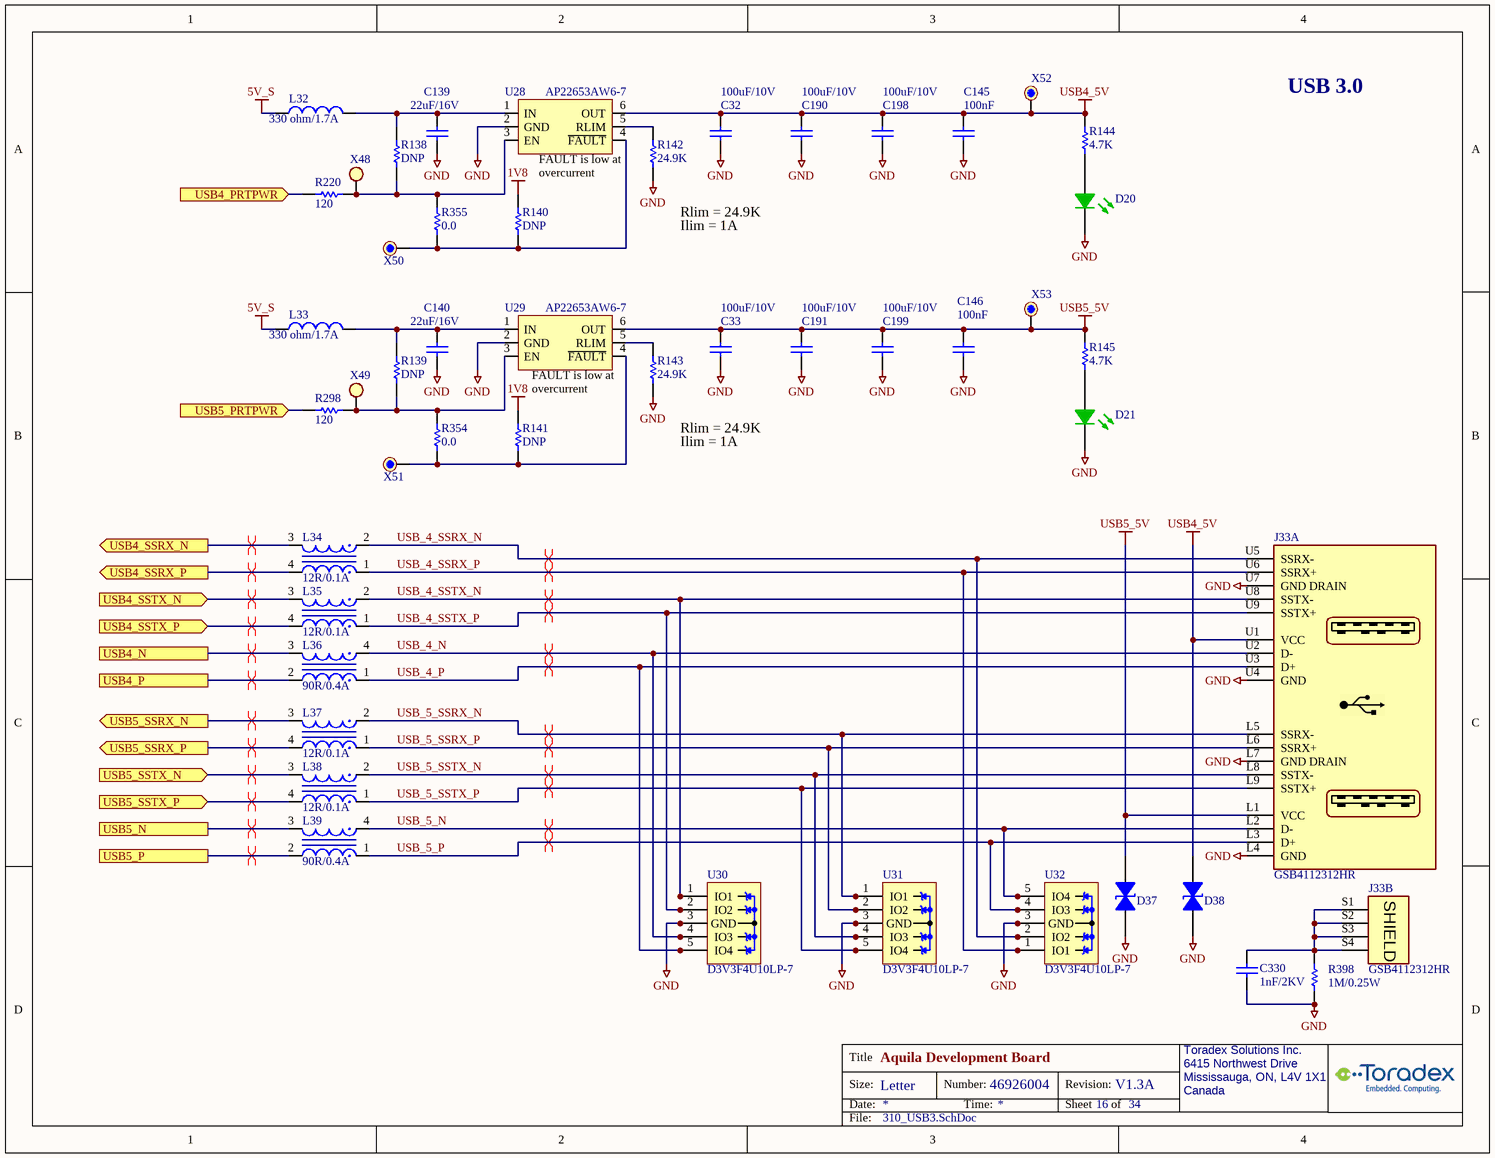
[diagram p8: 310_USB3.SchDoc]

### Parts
C32  100uF/10V  [C/1206]
C33  100uF/10V  [C/1206]
C139  value 22uF/16V  [C/0805]  (hidden comment: 22uF/6.3V)
C140  value 22uF/16V  [C/0805]  (hidden comment: 22uF/6.3V)
C145  100nF  [C0402_CAPC1005L]
C146  100nF  [C0402_CAPC1005L]
C190  100uF/10V  [C/1206]
C191  100uF/10V  [C/1206]
C198  100uF/10V  [C/1206]
C199  100uF/10V  [C/1206]
C330  value 1nF/2KV  [C/1206]  (hidden comment: 0567-Cap-1206-1nF/2KV)
D20  Status  [LED-SMT-0603_APT1608CGCK]  (value not drawn)
D21  Status  [LED-SMT-0603_APT1608CGCK]  (value not drawn)
D37  D5V0L1B2S9-7  [SOD923_DIO]  (value not drawn)
D38  D5V0L1B2S9-7  [SOD923_DIO]  (value not drawn)
J33  GSB4112312HR  [T_AMPHENOL_ GSB311231HR]  (parts A,B of 2)
L32  value 330 ohm/1.7A  [C/0603]  (hidden comment: 0405-Fer-0603-330ohm/1.7A)
L33  value 330 ohm/1.7A  [C/0603]  (hidden comment: 0405-Fer-0603-330ohm/1.7A)
L34  12R/0.1A  [COIL0302]
L35  12R/0.1A  [COIL0302]
L36  90R/0.4A  [COMMON_CHOKE_BOURNS_SRF2012-900YA]
L37  12R/0.1A  [COIL0302]
L38  12R/0.1A  [COIL0302]
L39  90R/0.4A  [COMMON_CHOKE_BOURNS_SRF2012-900YA]
R138  value DNP  [R/0603]  (hidden comment: 0000-Res-0603-DNP)
R139  value DNP  [R/0603]  (hidden comment: 0000-Res-0603-DNP)
R140  value DNP  [R0402_RESC1005L]  (hidden comment: 0000-Res-0402-DNP)
R141  value DNP  [R0402_RESC1005L]  (hidden comment: 0000-Res-0402-DNP)
R142  value 24.9K  [R/0603]  (hidden comment: 1144-Res-0603-24.9K)
R143  value 24.9K  [R/0603]  (hidden comment: 1144-Res-0603-24.9K)
R144  value 4.7K  [R0402_RESC1005L]  (hidden comment: 2233-Res-0402-4.7K)
R145  value 4.7K  [R0402_RESC1005L]  (hidden comment: 2233-Res-0402-4.7K)
R220  value 120  [R0402_RESC1005L]  (hidden comment: 1552-Res-0402-120)
R298  value 120  [R0402_RESC1005L]  (hidden comment: 1552-Res-0402-120)
R354  value 0.0  [R/0603]  (hidden comment: 0195-Res-0603-0.0ohm)
R355  value 0.0  [R/0603]  (hidden comment: 0195-Res-0603-0.0ohm)
R398  value 1M/0.25W  [R/1206]  (hidden comment: 1860-Res-1206-1M-5%-0.25W)
U28  AP22653AW6-7  [sot23-6]
U29  AP22653AW6-7  [sot23-6]
U30  D3V3F4U10LP-7  [10-UFDFN]
U31  D3V3F4U10LP-7  [10-UFDFN]
U32  D3V3F4U10LP-7  [10-UFDFN]
X48  000-TestPoint2  [TestPoint_3]  (value not drawn)
X49  000-TestPoint2  [TestPoint_3]  (value not drawn)
X50  000-TestPoint  [TestPoint_1]  (value not drawn)
X51  000-TestPoint  [TestPoint_1]  (value not drawn)
X52  000-TestPoint  [TestPoint_1]  (value not drawn)
X53  000-TestPoint  [TestPoint_1]  (value not drawn)

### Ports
USB4_N, USB4_P, USB4_PRTPWR (in), USB4_SSRX_N (out), USB4_SSRX_P (out), USB4_SSTX_N (in), USB4_SSTX_P (in), USB5_N, USB5_P, USB5_PRTPWR (in), USB5_SSRX_N (out), USB5_SSRX_P (out), USB5_SSTX_N (in), USB5_SSTX_P (in)

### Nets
1V8: R140.1 R141.1
5V_S: L32.1 L33.1
GND: C32.1 C33.1 C139.1 C140.1 C145.1 C146.1 C190.1 C191.1 C198.1 C199.1 C330.1 D20.2(K) D21.2(K) D37.1 D38.1 J33.L4(GND) J33.L7(GND_DRAIN) J33.U4(GND) J33.U7(GND_DRAIN) R142.1 R143.1 R398.2 U28.2(GND) U29.2(GND) U30.3(GND) U30.8(GND) U31.3(GND) U31.8(GND) U32.3(GND) U32.8(GND)
USB4_5V: C32.2 C145.2 C190.2 C198.2 D38.2 J33.U1(VCC) R144.2 U28.6(OUT) X52.1
USB5_5V: C33.2 C146.2 C191.2 C199.2 D37.2 J33.L1(VCC) R145.2 U29.6(OUT) X53.1
USB4_N: L36.3 ; port USB4_N
USB4_P: L36.2 ; port USB4_P
USB4_PRTPWR: R220.2 ; port USB4_PRTPWR
USB4_SSRX_N: L34.3 ; port USB4_SSRX_N
USB4_SSRX_P: L34.4 ; port USB4_SSRX_P
USB4_SSTX_N: L35.3 ; port USB4_SSTX_N
USB4_SSTX_P: L35.4 ; port USB4_SSTX_P
USB5_N: L39.3 ; port USB5_N
USB5_P: L39.2 ; port USB5_P
USB5_PRTPWR: R298.2 ; port USB5_PRTPWR
USB5_SSRX_N: L37.3 ; port USB5_SSRX_N
USB5_SSRX_P: L37.4 ; port USB5_SSRX_P
USB5_SSTX_N: L38.3 ; port USB5_SSTX_N
USB5_SSTX_P: L38.4 ; port USB5_SSTX_P
USB_4_N: J33.U2(D-) L36.4 U30.4(IO3) U30.7(NC)
USB_4_P: J33.U3(D+) L36.1 U30.5(IO4) U30.6(NC)
USB_4_SSRX_N: J33.U5(SSRX-) L34.2 U32.2(IO2) U32.9(NC)
USB_4_SSRX_P: J33.U6(SSRX+) L34.1 U32.1(IO1) U32.10(NC)
USB_4_SSTX_N: J33.U8(SSTX-) L35.2 U30.1(IO1) U30.10(NC)
USB_4_SSTX_P: J33.U9(SSTX+) L35.1 U30.2(IO2) U30.9(NC)
USB_5_N: J33.L2(D-) L39.4 U32.5(IO4) U32.6(NC)
USB_5_P: J33.L3(D+) L39.1 U32.4(IO3) U32.7(NC)
USB_5_SSRX_N: J33.L5(SSRX-) L37.2 U31.1(IO1) U31.10(NC)
USB_5_SSRX_P: J33.L6(SSRX+) L37.1 U31.2(IO2) U31.9(NC)
USB_5_SSTX_N: J33.L8(SSTX-) L38.2 U31.4(IO3) U31.7(NC)
USB_5_SSTX_P: J33.L9(SSTX+) L38.1 U31.5(IO4) U31.6(NC)
NetC139_2: C139.2 L32.2 R138.2 U28.1(IN)
NetC140_2: C140.2 L33.2 R139.2 U29.1(IN)
NetC330_2: C330.2 J33.S1(SHIELD) J33.S2(SHIELD) J33.S3(SHIELD) J33.S4(SHIELD) R398.1
NetD20_1: D20.1(A) R144.1
NetD21_1: D21.1(A) R145.1
NetR138_1: R138.1 R220.1 R355.2 U28.3(EN) X48.1
NetR139_1: R139.1 R298.1 R354.2 U29.3(EN) X49.1
NetR140_2: R140.2 R355.1 U28.4(~{FAULT}) X50.1
NetR141_2: R141.2 R354.1 U29.4(~{FAULT}) X51.1
NetR142_2: R142.2 U28.5(RLIM)
NetR143_2: R143.2 U29.5(RLIM)

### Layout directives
differential pair: USB4_N, USB4_P, USB4_SSRX_N, USB4_SSRX_P, USB4_SSTX_N, USB4_SSTX_P, USB5_N, USB5_P, USB5_SSRX_N, USB5_SSRX_P, USB5_SSTX_N, USB5_SSTX_P
differential pair; differential pair class USB_4_SS_CON: USB_4_SSRX_N, USB_4_SSRX_P, USB_4_SSTX_N, USB_4_SSTX_P
differential pair; differential pair class USB_5_CON: USB_5_N, USB_5_P
differential pair; differential pair class USB_5_SS_CON: USB_5_SSRX_N, USB_5_SSRX_P, USB_5_SSTX_N, USB_5_SSTX_P
differential pair; differential pair class USB_4_CON: USB_4_N, USB_4_P

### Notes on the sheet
- USB 3.0
- FAULT is low at
- overcurrent
- Rlim = 24.9K
- Ilim = 1A
- (near U29) FAULT is low at

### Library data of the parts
C32 C33 C190 C191 C198 C199 = 2282-Cap-1206-100uF/10V: as C28 on sheet 300_USB1_OTG
C139 C140 = 1314-Cap-0805-22uF/16V: (-55 to 85 DegC) CAP CER 22uF 16V X5R 0805; MfrNo: CL21A226MOQNNNE; Mfr: Samsung; PN: 1314; Alt: CL21A226MOCLRNC,CL21A226KOQNNNG,GRM21BR61C226ME44L,EMK212BBJ226MG-T
C145 C146 = 1566-Cap-0402-100nF/50V: as C65-C70 on sheet 210_Translators
C330 = 0567-Cap-1206-1nF/2KV: as C71 on sheet 220_Debug
D20 D21 = 0333-LED Green 0603: as D11 on sheet 220_Debug
D37 D38 = 1655-D5V0L1B2S9-7: as D50 on sheet 300_USB1_OTG
J33 = 1820-Conn-USB3-2x-RA: (-40 to 85 DegC) Conn USB 3.1 Type A R/A TH; Mfr: Amphenol Commercial; PN: 1820
L32 L33 = 0405-Fer-0603-330ohm/1.7A: as L13 on sheet 220_Debug
L34 L35 L37 L38 = 1371-Ind-0.8x0.6-12ohm/0.1A-Choke: as L22 on sheet 300_USB1_OTG
L36 L39 = 0277-Ind-2x1.2-90ohm/0.4A-Choke: as L14 on sheet 220_Debug
R138 R139 = 0000-Res-0603-DNP: RES 0603
R140 R141 = 0000-Res-0402-DNP: RES 0402
R142 R143 = 1144-Res-0603-24.9K: (-55 to 155 DegC) RES SMD 24.9K OHM 1% 1/10W 0603 100ppm; MfrNo: RMCF0603FT24K9; Mfr: Stackpole Electronics; Alt: CR0603-FX-2492ELF,RC0603FR-0724K9L; PN: 1144
R144 R145 = 2233-Res-0402-4.7K: as R71-R74 on sheet 210_Translators
R220 R298 = 1552-Res-0402-120: (-55 to 155 DegC AEC) RES 120 OHM 1% 1/16W 100ppm 0402; MfrNo: RMCF0402FT120R; Mfr: Stackpole Electronics; PN: 1552; Alt: AC0402FR-07120RL,CRGCQ0402F120R
R354 R355 = 0195-Res-0603-0.0ohm: as R110 on sheet 300_USB1_OTG
R398 = 1860-Res-1206-1M-5%-0.25W: as R82 on sheet 220_Debug
U28 U29 = 1475-AP22653: (-40 to 85 DegC) IC PWR SWITCH 3-5.5V EN-Active-High ENth:1.5V With-Discharge 65mohm typ ADJ 0.1-2.1A 6SSOP; Mfr: Diodes; PN: 1475; Note: Similar: BD2222G, BD2242G, TPS25221, TPS2553, RT9728A, RT9728B, RT9728C, AP2553, MIC2009YM6, MIC2019YM6, MIC2009A-1YM6,MIC2019A-1YM6
U30-U32 = 1463-D3V3F4U10LP: as U20 on sheet 300_USB1_OTG
X48 X49 = 000-TestPoint2: as X36 on sheet 300_USB1_OTG
X50-X53 = 000-TestPoint: as X29 on sheet 220_Debug

## Sheet 305_USB_Hub.SchDoc: Aquila Development Board
size A3; Organization: Toradex Solutions Inc.; Address1: 6415 Northwest Drive; Address2: Mississauga, ON, L4V 1X1; Address3: Canada; SheetNumber: 15; SheetTotal: 34
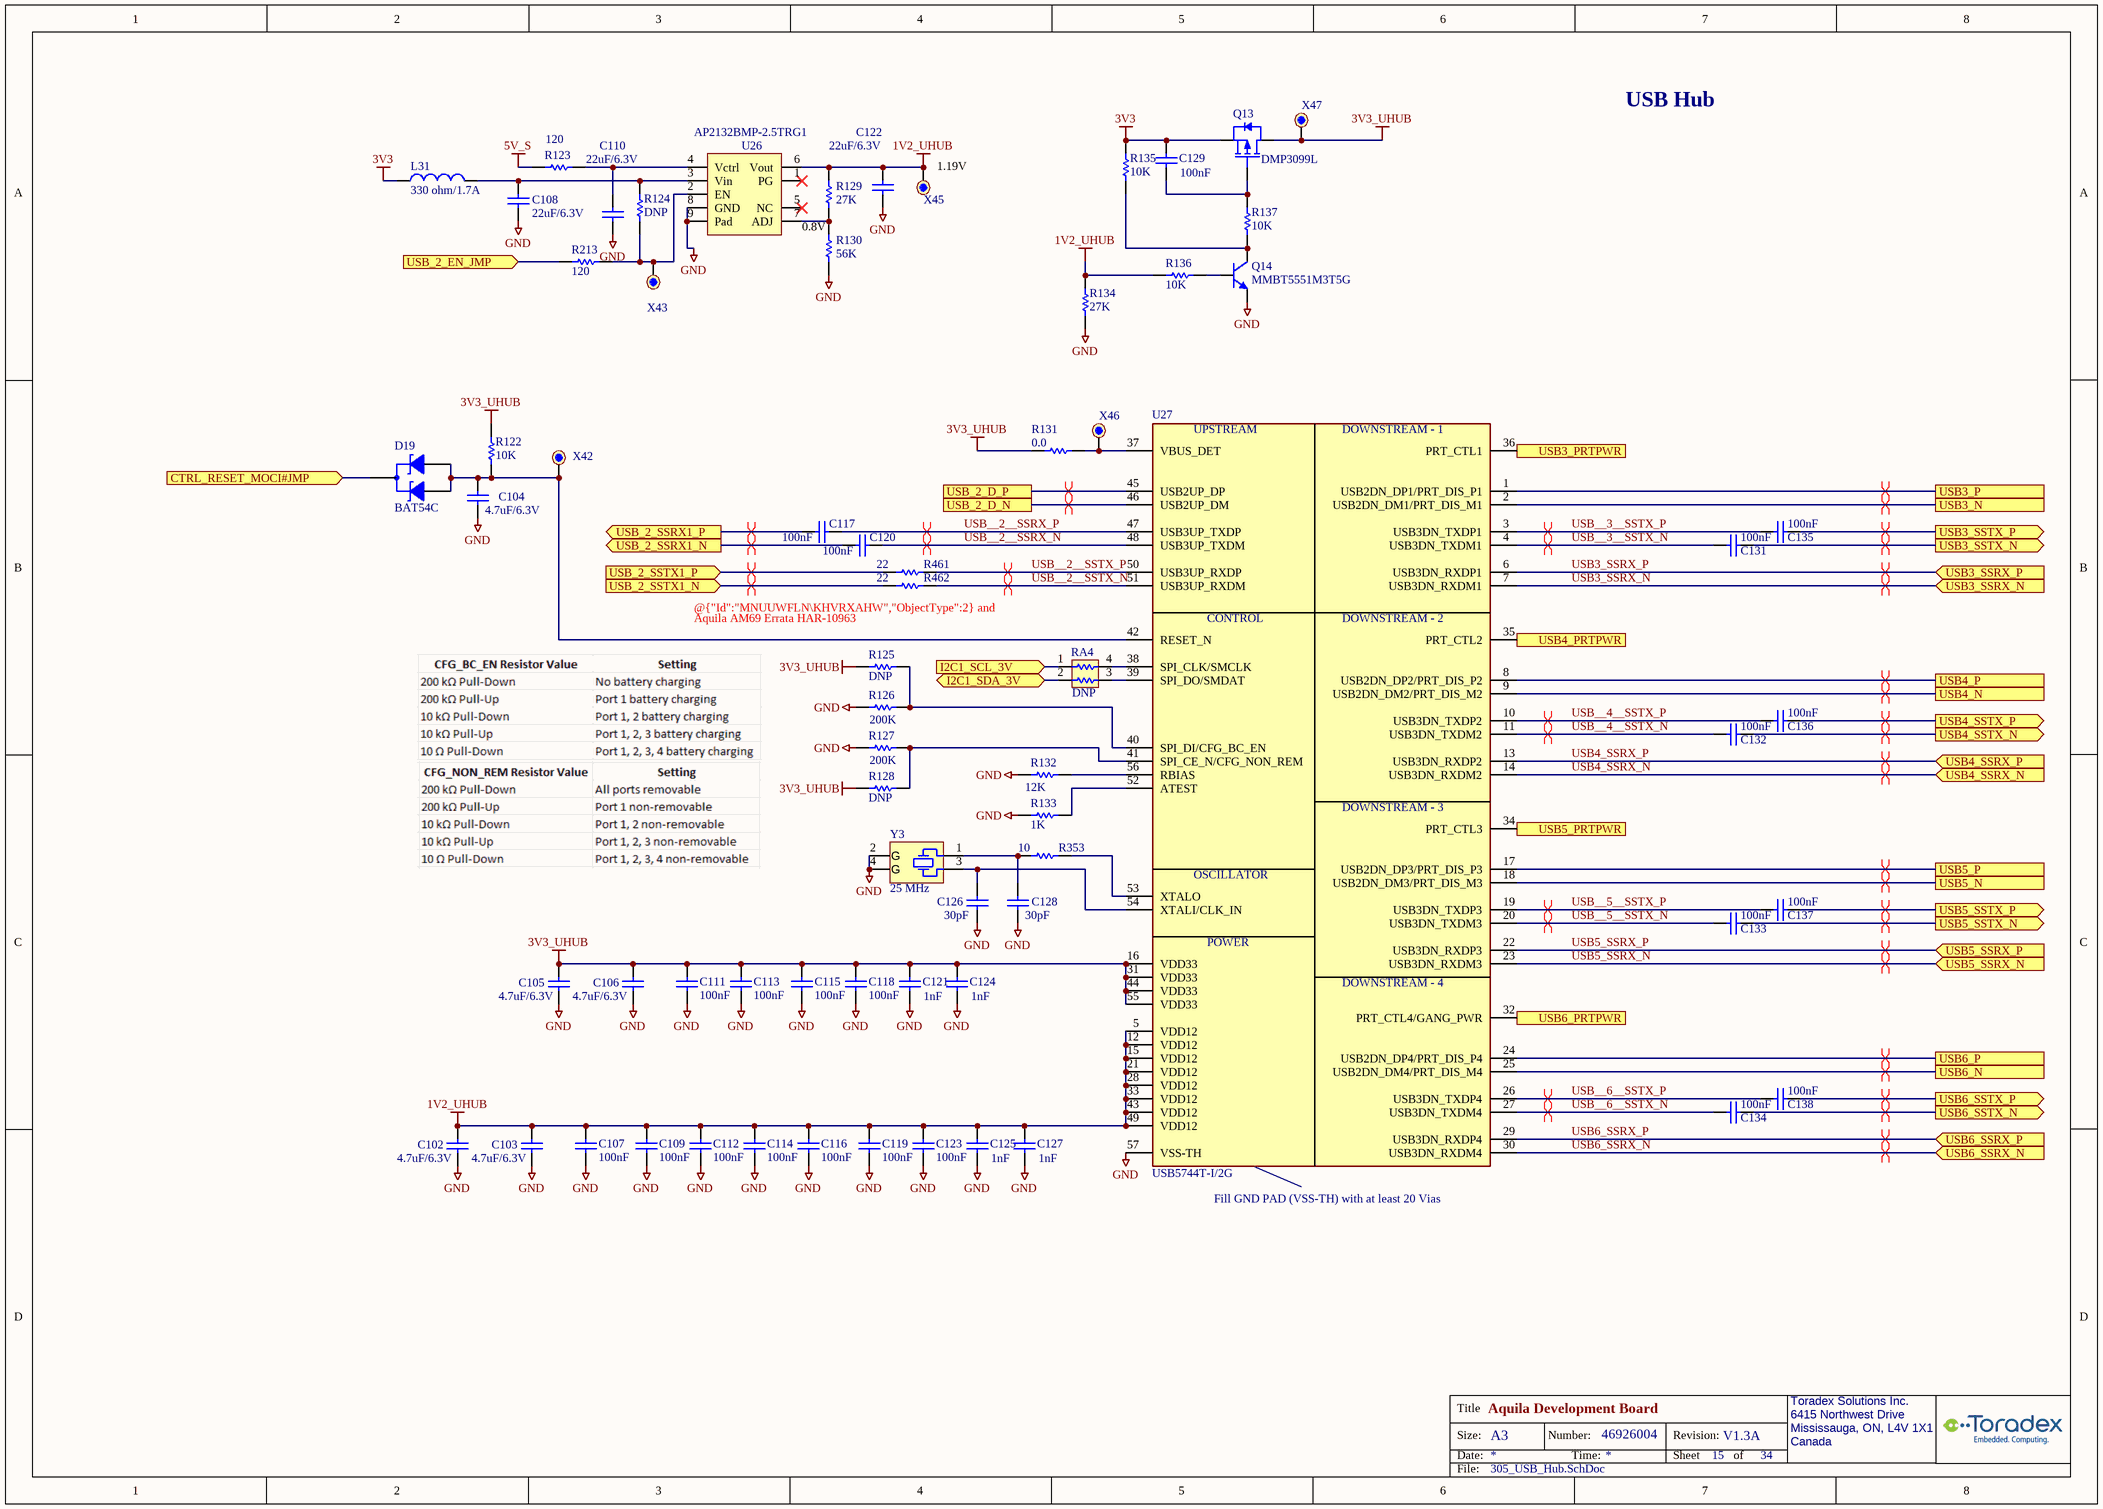
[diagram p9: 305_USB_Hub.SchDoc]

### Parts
C102  value 4.7uF/6.3V  [C0402_CAPC1005L]  (hidden comment: 0354-Cap-0402-4.7uF/6.3V)
C103  value 4.7uF/6.3V  [C0402_CAPC1005L]  (hidden comment: 0354-Cap-0402-4.7uF/6.3V)
C104  value 4.7uF/6.3V  [C0402_CAPC1005L]  (hidden comment: 0354-Cap-0402-4.7uF/6.3V)
C105  value 4.7uF/6.3V  [C0402_CAPC1005L]  (hidden comment: 0354-Cap-0402-4.7uF/6.3V)
C106  value 4.7uF/6.3V  [C0402_CAPC1005L]  (hidden comment: 0354-Cap-0402-4.7uF/6.3V)
C107  100nF  [C0402_CAPC1005L]
C108  22uF/6.3V  [C0402_CAPC1005L]
C109  100nF  [C0402_CAPC1005L]
C110  22uF/6.3V  [C0402_CAPC1005L]
C111  100nF  [C0402_CAPC1005L]
C112  100nF  [C0402_CAPC1005L]
C113  100nF  [C0402_CAPC1005L]
C114  100nF  [C0402_CAPC1005L]
C115  100nF  [C0402_CAPC1005L]
C116  100nF  [C0402_CAPC1005L]
C117  100nF  [C0402_CAPC1005L]
C118  100nF  [C0402_CAPC1005L]
C119  100nF  [C0402_CAPC1005L]
C120  100nF  [C0402_CAPC1005L]
C121  value 1nF  [C0402_CAPC1005L]  (hidden comment: 0318-Cap-0402-1nF/50V)
C122  22uF/6.3V  [C0402_CAPC1005L]
C123  100nF  [C0402_CAPC1005L]
C124  value 1nF  [C0402_CAPC1005L]  (hidden comment: 0318-Cap-0402-1nF/50V)
C125  value 1nF  [C0402_CAPC1005L]  (hidden comment: 0318-Cap-0402-1nF/50V)
C126  value 30pF  [C0402_CAPC1005L]  (hidden comment: 1554-Cap-0402-30pF)
C127  value 1nF  [C0402_CAPC1005L]  (hidden comment: 0318-Cap-0402-1nF/50V)
C128  value 30pF  [C0402_CAPC1005L]  (hidden comment: 1554-Cap-0402-30pF)
C129  100nF  [C0402_CAPC1005L]
C131  100nF  [C0402_CAPC1005L]
C132  100nF  [C0402_CAPC1005L]
C133  100nF  [C0402_CAPC1005L]
C134  100nF  [C0402_CAPC1005L]
C135  100nF  [C0402_CAPC1005L]
C136  100nF  [C0402_CAPC1005L]
C137  100nF  [C0402_CAPC1005L]
C138  100nF  [C0402_CAPC1005L]
D19  BAT54C  [SOT23_M]
L31  value 330 ohm/1.7A  [C/0603]  (hidden comment: 0405-Fer-0603-330ohm/1.7A)
Q13  DMP3099L  [SOT23_N]
Q14  MMBT5551M3T5G  [SOT-723_0P85X1P25_ONS]
R122  value 10K  [R0402_RESC1005L]  (hidden comment: 1572-Res-0402-10K)
R123  value 120  [R0402_RESC1005L]  (hidden comment: 1552-Res-0402-120)
R124  value DNP  [R/0603]  (hidden comment: 0000-Res-0603-DNP)
R125  value DNP  [R0402_RESC1005L]  (hidden comment: 0000-Res-0402-DNP)
R126  value 200K  [R0402_RESC1005L]  (hidden comment: 1540-Res-0402-200k)
R127  value 200K  [R0402_RESC1005L]  (hidden comment: 1540-Res-0402-200k)
R128  value DNP  [R0402_RESC1005L]  (hidden comment: 0000-Res-0402-DNP)
R129  value 27K  [R0402_RESC1005L]  (hidden comment: 1538-Res-0402-27k)
R130  value 56K  [R/0603]  (hidden comment: 0342-Res-0603-56K)
R131  value 0.0  [R/0603]  (hidden comment: 0195-Res-0603-0.0ohm)
R132  value 12K  [R0402_RESC1005L]  (hidden comment: 1537-Res-0402-12K)
R133  value 1K  [R0402_RESC1005L]  (hidden comment: 1650-Res-0402-1K)
R134  value 27K  [R0402_RESC1005L]  (hidden comment: 1538-Res-0402-27k)
R135  value 10K  [R0402_RESC1005L]  (hidden comment: 1572-Res-0402-10K)
R136  value 10K  [R0402_RESC1005L]  (hidden comment: 1572-Res-0402-10K)
R137  value 10K  [R0402_RESC1005L]  (hidden comment: 1572-Res-0402-10K)
R213  value 120  [R0402_RESC1005L]  (hidden comment: 1552-Res-0402-120)
R353  value 10  [R0402_RESC1005L]  (hidden comment: 0257-Res-0402-10ohm)
R461  value 22  [R0402_RESC1005L]  (hidden comment: 0703-Res-0402-22ohm)
R462  value 22  [R0402_RESC1005L]  (hidden comment: 0703-Res-0402-22ohm)
RA4  value DNP  [EXB34V]  (hidden comment: 0000-ResArr-0606-DNP)
U26  AP2132BMP-2.5TRG1  [SOP-9 TP_ALT]
U27  USB5744T-I/2G  [56-VQFN (7x7)]
X42  000-TestPoint  [TestPoint_1]  (value not drawn)
X43  000-TestPoint  [TestPoint_1]  (value not drawn)
X45  000-TestPoint  [TestPoint_1]  (value not drawn)
X46  000-TestPoint  [TestPoint_1]  (value not drawn)
X47  000-TestPoint  [TestPoint_1]  (value not drawn)
Y3  value 25 MHz  [XTAL_CX3225]  (hidden comment: 0987-Xtal 25MHz 3.2x2.5mm)

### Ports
CTRL_RESET_MOCI#JMP (in), I2C1_SCL_3V (in), I2C1_SDA_3V (bidir), USB3_N, USB3_P, USB3_PRTPWR (out), USB3_SSRX_N (in), USB3_SSRX_P (in), USB3_SSTX_N (out), USB3_SSTX_P (out), USB4_N, USB4_P, USB4_PRTPWR (out), USB4_SSRX_N (in), USB4_SSRX_P (in), USB4_SSTX_N (out), USB4_SSTX_P (out), USB5_N, USB5_P, USB5_PRTPWR (out), USB5_SSRX_N (in), USB5_SSRX_P (in), USB5_SSTX_N (out), USB5_SSTX_P (out), USB6_N, USB6_P, USB6_PRTPWR (out), USB6_SSRX_N (in), USB6_SSRX_P (in), USB6_SSTX_N (out), USB6_SSTX_P (out), USB_2_D_N, USB_2_D_P, USB_2_EN_JMP (in), USB_2_SSRX1_N (out), USB_2_SSRX1_P (out), USB_2_SSTX1_N (in), USB_2_SSTX1_P (in)

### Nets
1V2_UHUB: C102.2 C103.2 C107.2 C109.2 C112.2 C114.2 C116.2 C119.2 C122.2 C123.2 C125.1 C127.1 R129.2 R134.2 R136.2 U26.6(Vout) U27.5(VDD12) U27.12(VDD12) U27.15(VDD12) U27.21(VDD12) U27.28(VDD12) U27.33(VDD12) U27.43(VDD12) U27.49(VDD12) X45.1
3V3: C129.2 L31.2 Q13.2(S) R135.2
3V3_UHUB: C105.2 C106.2 C111.2 C113.2 C115.2 C118.2 C121.1 C124.1 Q13.3(D) R122.1 R125.2 R128.2 R131.1 U27.16(VDD33) U27.31(VDD33) U27.44(VDD33) U27.55(VDD33) X47.1
5V_S: R123.2
GND: C102.1 C103.1 C104.1 C105.1 C106.1 C107.1 C108.1 C109.1 C110.1 C111.1 C112.1 C113.1 C114.1 C115.1 C116.1 C118.1 C119.1 C121.2 C122.1 C123.1 C124.2 C125.2 C126.2 C127.2 C128.2 Q14.2(E) R126.1 R127.1 R130.2 R132.1 R133.1 R134.1 U26.8(GND) U26.9(Pad) U27.57(VSS-TH) Y3.2(GND) Y3.4(GND)
CTRL_RESET_MOCI#JMP: D19.3(K) ; port CTRL_RESET_MOCI#JMP
I2C1_SCL_3V: RA4.1 ; port I2C1_SCL_3V
I2C1_SDA_3V: RA4.2 ; port I2C1_SDA_3V
USB3_N: U27.2(USB2DN_DM1/PRT_DIS_M1) ; port USB3_N
USB3_P: U27.1(USB2DN_DP1/PRT_DIS_P1) ; port USB3_P
USB3_PRTPWR: U27.36(PRT_CTL1) ; port USB3_PRTPWR
USB3_SSRX_N: U27.7(USB3DN_RXDM1) ; port USB3_SSRX_N
USB3_SSRX_P: U27.6(USB3DN_RXDP1) ; port USB3_SSRX_P
USB3_SSTX_N: C131.1 ; port USB3_SSTX_N
USB3_SSTX_P: C135.1 ; port USB3_SSTX_P
USB4_N: U27.9(USB2DN_DM2/PRT_DIS_M2) ; port USB4_N
USB4_P: U27.8(USB2DN_DP2/PRT_DIS_P2) ; port USB4_P
USB4_PRTPWR: U27.35(PRT_CTL2) ; port USB4_PRTPWR
USB4_SSRX_N: U27.14(USB3DN_RXDM2) ; port USB4_SSRX_N
USB4_SSRX_P: U27.13(USB3DN_RXDP2) ; port USB4_SSRX_P
USB4_SSTX_N: C132.1 ; port USB4_SSTX_N
USB4_SSTX_P: C136.1 ; port USB4_SSTX_P
USB5_N: U27.18(USB2DN_DM3/PRT_DIS_M3) ; port USB5_N
USB5_P: U27.17(USB2DN_DP3/PRT_DIS_P3) ; port USB5_P
USB5_PRTPWR: U27.34(PRT_CTL3) ; port USB5_PRTPWR
USB5_SSRX_N: U27.23(USB3DN_RXDM3) ; port USB5_SSRX_N
USB5_SSRX_P: U27.22(USB3DN_RXDP3) ; port USB5_SSRX_P
USB5_SSTX_N: C133.1 ; port USB5_SSTX_N
USB5_SSTX_P: C137.1 ; port USB5_SSTX_P
USB6_N: U27.25(USB2DN_DM4/PRT_DIS_M4) ; port USB6_N
USB6_P: U27.24(USB2DN_DP4/PRT_DIS_P4) ; port USB6_P
USB6_PRTPWR: U27.32(PRT_CTL4/GANG_PWR) ; port USB6_PRTPWR
USB6_SSRX_N: U27.30(USB3DN_RXDM4) ; port USB6_SSRX_N
USB6_SSRX_P: U27.29(USB3DN_RXDP4) ; port USB6_SSRX_P
USB6_SSTX_N: C134.1 ; port USB6_SSTX_N
USB6_SSTX_P: C138.1 ; port USB6_SSTX_P
USB_2_D_N: U27.46(USB2UP_DM) ; port USB_2_D_N
USB_2_D_P: U27.45(USB2UP_DP) ; port USB_2_D_P
USB_2_EN_JMP: R213.2 ; port USB_2_EN_JMP
USB_2_SSRX1_N: C120.1 ; port USB_2_SSRX1_N
USB_2_SSRX1_P: C117.1 ; port USB_2_SSRX1_P
USB_2_SSTX1_N: R462.1 ; port USB_2_SSTX1_N
USB_2_SSTX1_P: R461.1 ; port USB_2_SSTX1_P
USB__2__SSRX_N: C120.2 U27.48(USB3UP_TXDM)
USB__2__SSRX_P: C117.2 U27.47(USB3UP_TXDP)
USB__2__SSTX_N: R462.2 U27.51(USB3UP_RXDM)
USB__2__SSTX_P: R461.2 U27.50(USB3UP_RXDP)
USB__3__SSTX_N: C131.2 U27.4(USB3DN_TXDM1)
USB__3__SSTX_P: C135.2 U27.3(USB3DN_TXDP1)
USB__4__SSTX_N: C132.2 U27.11(USB3DN_TXDM2)
USB__4__SSTX_P: C136.2 U27.10(USB3DN_TXDP2)
USB__5__SSTX_N: C133.2 U27.20(USB3DN_TXDM3)
USB__5__SSTX_P: C137.2 U27.19(USB3DN_TXDP3)
USB__6__SSTX_N: C134.2 U27.27(USB3DN_TXDM4)
USB__6__SSTX_P: C138.2 U27.26(USB3DN_TXDP4)
NetC104_2: C104.2 D19.1(A1) D19.2(A2) R122.2 U27.42(RESET_N) X42.1
NetC108_2: C108.2 L31.1 R124.1 U26.3(Vin)
NetC110_2: C110.2 R123.1 U26.4(Vctrl)
NetC126_1: C126.1 U27.54(XTALI/CLK_IN) Y3.3
NetC128_1: C128.1 R353.2 Y3.1
NetC129_1: C129.1 Q13.1(G) R137.2
NetQ14_1: Q14.1(B) R136.1
NetQ14_3: Q14.3(C) R135.1 R137.1
NetR124_2: R124.2 R213.1 U26.2(EN) X43.1
NetR125_1: R125.1 R126.2 U27.40(SPI_DI/CFG_BC_EN)
NetR127_2: R127.2 R128.1 U27.41(SPI_CE_N/CFG_NON_REM)
NetR129_1: R129.1 R130.1 U26.7(ADJ)
NetR131_2: R131.2 U27.37(VBUS_DET) X46.1
NetR132_2: R132.2 U27.56(RBIAS)
NetR133_2: R133.2 U27.52(ATEST)
NetR353_1: R353.1 U27.53(XTALO)
NetRA4_3: RA4.3 U27.39(SPI_DO/SMDAT)
NetRA4_4: RA4.4 U27.38(SPI_CLK/SMCLK)

Not connected (* = marked no-connect by the designer): U26 1(PG)* 5(NC)*

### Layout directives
differential pair: USB_2_D_N, USB_2_D_P
differential pair; differential pair class USB_2_SSRX_HUB: USB__2__SSRX_N, USB__2__SSRX_P
differential pair; differential pair class USB_3_SS_HUB: USB__3__SSTX_N, USB__3__SSTX_P
differential pair; differential pair class USB_3: USB3_N, USB3_P
differential pair; differential pair class USB_3_SSRX: USB3_SSRX_N, USB3_SSRX_P
differential pair; differential pair class USB_4_SS_HUB: USB__4__SSTX_N, USB__4__SSTX_P
differential pair; differential pair class USB_5_SS_HUB: USB__5__SSTX_N, USB__5__SSTX_P
differential pair; differential pair class USB_6_SS_HUB: USB__6__SSTX_N, USB__6__SSTX_P
differential pair; differential pair class USB_4: USB4_N, USB4_P
differential pair; differential pair class USB_4_SSRX: USB4_SSRX_N, USB4_SSRX_P
differential pair; differential pair class USB_5: USB5_N, USB5_P
differential pair; differential pair class USB_5_SSRX: USB5_SSRX_N, USB5_SSRX_P
differential pair; differential pair class USB_6: USB6_N, USB6_P
differential pair; differential pair class USB_6_SSRX: USB6_SSRX_N, USB6_SSRX_P
differential pair; differential pair class USB_3_SSTX: USB3_SSTX_N, USB3_SSTX_P
differential pair; differential pair class USB_4_SSTX: USB4_SSTX_N, USB4_SSTX_P
differential pair; differential pair class USB_5_SSTX: USB5_SSTX_N, USB5_SSTX_P
differential pair; differential pair class USB_6_SSTX: USB6_SSTX_N, USB6_SSTX_P
differential pair; differential pair class USB_2_SSRX1: USB_2_SSRX1_N, USB_2_SSRX1_P
differential pair; differential pair class USB_2_SSTX1: USB_2_SSTX1_N, USB_2_SSTX1_P
differential pair; differential pair class USB_2_SSTX_HUB: USB__2__SSTX_N, USB__2__SSTX_P

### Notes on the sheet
- USB Hub
- (near X45) 1.19V
- (near R130) 0.8V
- (near U27) @{"Id":"MNUUWFLN\KHVRXAHW","ObjectType":2} and @{"Id":"MNUUWFLN\VJSQZSGG","ObjectType":2} assembled as 100nF capacitors due to missing caps on Aquila SOM V1.0
- Aquila AM69 Errata HAR-10963
- (near U27) Fill GND PAD (VSS-TH) with at least 20 Vias

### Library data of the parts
C102-C106 = 0354-Cap-0402-4.7uF/6.3V: as C94 on sheet 300_USB1_OTG
C107 C109 C111-C120 C123 C131-C138 = 1566-Cap-0402-100nF/50V: (-55 to 125 DegC AEC) Cap Ceramic 0.1uF 50V X7R 10% 0402; Mfr: Murata; MfrNo: GRT155R71H104KE01D; Alt: CL05B104KB54PNC,GCM155R71H104ME02D,GCM155R71H104KE02D,GCM155R71H104KE02J; PN: 1566
C108 C110 C122 = 2404-Cap-0402-22uF/6.3V: as C39 on sheet 220_Debug
C121 C124 C125 C127 = 0318-Cap-0402-1nF/50V: (-55 to 125 DegC) CAP CER 1000PF 50V 5% NP0 0402; Mfr: Samsung Electro-Mechanics America, Inc; MfrNo: CL05C102JB5NNNC; Alt: 399-10034-1-ND; Alt2: 490-3244-1-ND; PN: 318
C126 C128 = 1554-Cap-0402-30pF: (-55 to 125 DegC AEC) CAP CER 30PF 5% 50V C0G/NPO 0402; Mfr: Murata; MfrNo: GCM1555C1H300JA16D; PN: 1554; Alt: AC0402JRNPO9BN300,GCM1555C1H300GA16D,GCM1555C1H300FA16D
C129 = 1566-Cap-0402-100nF/50V: as C65-C70 on sheet 210_Translators
D19 = 0242B-BAT54C: as D12 on sheet 220_Debug
L31 = 0405-Fer-0603-330ohm/1.7A: as L13 on sheet 220_Debug
Q13 = 0186-DMP3099L: (-55 to 150 DegC) MOSFET P-CH 30V 3.8A 65mohm SOT23; MfrNo: DMP3099L-7; Mfr: Diodes Incorporated; PN: 186
Q14 = 1857-MMBT5551M3T5G: (-55 to 150 DegC) TRANS NPN 160V 60mA 1.2x1.2 SOT723; Mfr: ON Semiconductor; PN: 1857
R122 R135-R137 = 1572-Res-0402-10K: as R108 on sheet 300_USB1_OTG
R123 R213 = 1552-Res-0402-120: as R220 on sheet 310_USB3
R124 = 0000-Res-0603-DNP: RES 0603
R125 R128 = 0000-Res-0402-DNP: RES 0402
R126 R127 = 1540-Res-0402-200k: as R69 on sheet 210_Translators
R129 R134 = 1538-Res-0402-27k: as R104 on sheet 300_USB1_OTG
R130 = 0342-Res-0603-56K: (-55 to 155 DegC) RES 56K OHM 1/10W 1% 0603; MfrNo: RC1608F563CS; Mfr: Samsung Electro-Mechanics America, Inc; Alt: 311-56KHRCT-ND; Alt2: RMCF0603FT56K0CT-ND; PN: 342; TR: 1276-4816-2-ND
R131 = 0195-Res-0603-0.0ohm: as R110 on sheet 300_USB1_OTG
R132 = 1537-Res-0402-12K: (-55 to 155 DegC AEC) RES 12K OHM 1% 1/16W 100ppm 0402; Mfr: Stackpole Electronics; MfrNo: RMCF0402FT12K0; Alt: AC0402FR-0712KL,CRGCQ0402F12K; PN: 1537
R133 = 1650-Res-0402-1K: (-55 to 155 DegC AEC) RES 1K OHM 1% 1/16W 100ppm 0402; MfrNo: CRGCQ0402F1K0; Mfr: TE Connectivity; Alt: CR0402AFX-1001GLF,AC0402FR-131KL,AC0402FR-071KL; PN: 1650
R353 = 0257-Res-0402-10ohm: (-55 to 155 DegC) RES 10 OHM 1/16W 1% 0402 SMD; Mfr: Rohm Semiconductor; MfrNo: MCR01MRTF10R0; Alt: 311-10.0LRCT-ND; Alt2: 1276-3428-1-ND; PN: 257
R461 R462 = 0703-Res-0402-22ohm: (-55 to 155 DegC) RES SMD 22 OHM 1% 1/16W 0402; MfrNo: GRT155R71H104KE01D; Mfr: Murata; PN: 1566
RA4 = 0000-ResArr-0606-DNP: RES ARRAY 2 RES 0606
U26 = 1467-AP2132BMP-2.5: (-40 to 85 DegC) IC REG LDO LINEAR POS ADJ 5V 2A 8SO; Mfr: Diodes; PN: 1467; Desc: (-40 to 85 DegC) IC REG BUCK ADJ Sync 5A Vin:3.8 to 40V 100-2200kHz FSS (spread spectrum) MaxDuty:100% SO-8EP; Note: These can be also used with adjust Voltage circuit: AP2132BMP-1.2TRG1, AP2132BMP-1.5TRG1
U27 = 1643-USB5744: (-40 to 85 DegC) IC 4 port USB3.2 HUB 56-VFQFN; Mfr: Microchip; PN: 1643
X42 X43 X45-X47 = 000-TestPoint: as X29 on sheet 220_Debug
Y3 = 0987-Xtal 25MHz 3.2x2.5mm: (-40 to 85 DegC) CRYSTAL 25.0MHZ 18PF SMD +-50ppm +-20ppm 3.2x2.5mm; MfrNo: LFXTAL055299REEL; Mfr: IQD Frequency Products; PN: 987; Note: caps: 18pF

## Sheet 350_Ethernet.SchDoc: Aquila Development Board
size Letter; Organization: Toradex Solutions Inc.; Address1: 6415 Northwest Drive; Address2: Mississauga, ON, L4V 1X1; Address3: Canada; SheetNumber: 19; SheetTotal: 34
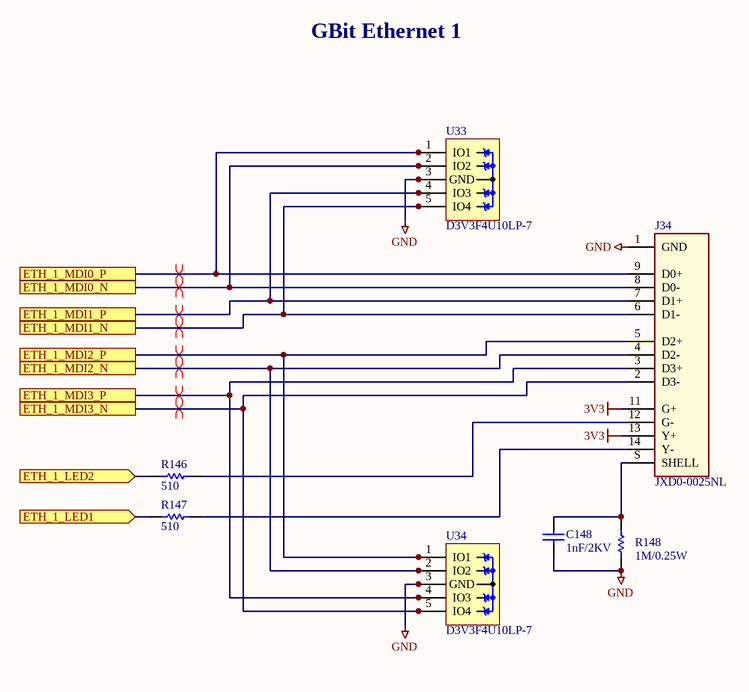
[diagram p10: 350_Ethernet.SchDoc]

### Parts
C148  value 1nF/2KV  [C/1206]  (hidden comment: 0567-Cap-1206-1nF/2KV)
J34  JXD0-0025NL  [PULSE_JXD0-0025NL]
R146  value 510  [R/0603]  (hidden comment: 0043-Res-0603-510ohm)
R147  value 510  [R/0603]  (hidden comment: 0043-Res-0603-510ohm)
R148  value 1M/0.25W  [R/1206]  (hidden comment: 1860-Res-1206-1M-5%-0.25W)
U33  D3V3F4U10LP-7  [10-UFDFN]
U34  D3V3F4U10LP-7  [10-UFDFN]

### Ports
ETH_1_LED1 (in), ETH_1_LED2 (in), ETH_1_MDI0_N, ETH_1_MDI0_P, ETH_1_MDI1_N, ETH_1_MDI1_P, ETH_1_MDI2_N, ETH_1_MDI2_P, ETH_1_MDI3_N, ETH_1_MDI3_P

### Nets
3V3: J34.11(G+) J34.13(Y+)
GND: C148.1 J34.1(GND) R148.2 U33.3(GND) U33.8(GND) U34.3(GND) U34.8(GND)
ETH_1_LED1: R147.1 ; port ETH_1_LED1
ETH_1_LED2: R146.1 ; port ETH_1_LED2
ETH_1_MDI0_N: J34.8(D0-) U33.2(IO2) U33.9(NC) ; port ETH_1_MDI0_N
ETH_1_MDI0_P: J34.9(D0+) U33.1(IO1) U33.10(NC) ; port ETH_1_MDI0_P
ETH_1_MDI1_N: J34.6(D1-) U33.5(IO4) U33.6(NC) ; port ETH_1_MDI1_N
ETH_1_MDI1_P: J34.7(D1+) U33.4(IO3) U33.7(NC) ; port ETH_1_MDI1_P
ETH_1_MDI2_N: J34.4(D2-) U34.2(IO2) U34.9(NC) ; port ETH_1_MDI2_N
ETH_1_MDI2_P: J34.5(D2+) U34.1(IO1) U34.10(NC) ; port ETH_1_MDI2_P
ETH_1_MDI3_N: J34.2(D3-) U34.5(IO4) U34.6(NC) ; port ETH_1_MDI3_N
ETH_1_MDI3_P: J34.3(D3+) U34.4(IO3) U34.7(NC) ; port ETH_1_MDI3_P
NetC148_2: C148.2 J34.S(SHELL) R148.1
NetJ34_12: J34.12(G-) R146.2
NetJ34_14: J34.14(Y-) R147.2

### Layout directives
differential pair: ETH_1_MDI0_N, ETH_1_MDI0_P, ETH_1_MDI1_N, ETH_1_MDI1_P, ETH_1_MDI2_N, ETH_1_MDI2_P, ETH_1_MDI3_N, ETH_1_MDI3_P

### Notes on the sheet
- GBit Ethernet 1

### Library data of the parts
C148 = 0567-Cap-1206-1nF/2KV: as C71 on sheet 220_Debug
J34 = 1380-Conn-RJ45-GBe: (-40 to 85 DegC) CONN MAGJACK 1PORT 1000 BASE-T Isolated Taps; Mfr: Pulse; PN: 1380
R146 R147 = 0043-Res-0603-510ohm: (-55 to 155 DegC) RES 510 OHM 1/10W 1% 0603 SMD; Mfr: Yageo; MfrNo: RC0603FR-07510RL; Alt: RHM510HCT-ND; Alt2: RMCF0603FT510RCT-ND; PN: 43; TR: 311-510HRTR-ND
R148 = 1860-Res-1206-1M-5%-0.25W: as R82 on sheet 220_Debug
U33 U34 = 1463-D3V3F4U10LP: as U20 on sheet 300_USB1_OTG

## Sheet 230_SD_Card.SchDoc: Aquila Development Board
size Letter; Organization: Toradex Solutions Inc.; Address1: 6415 Northwest Drive; Address2: Mississauga, ON, L4V 1X1; Address3: Canada; SheetNumber: 13; SheetTotal: 34
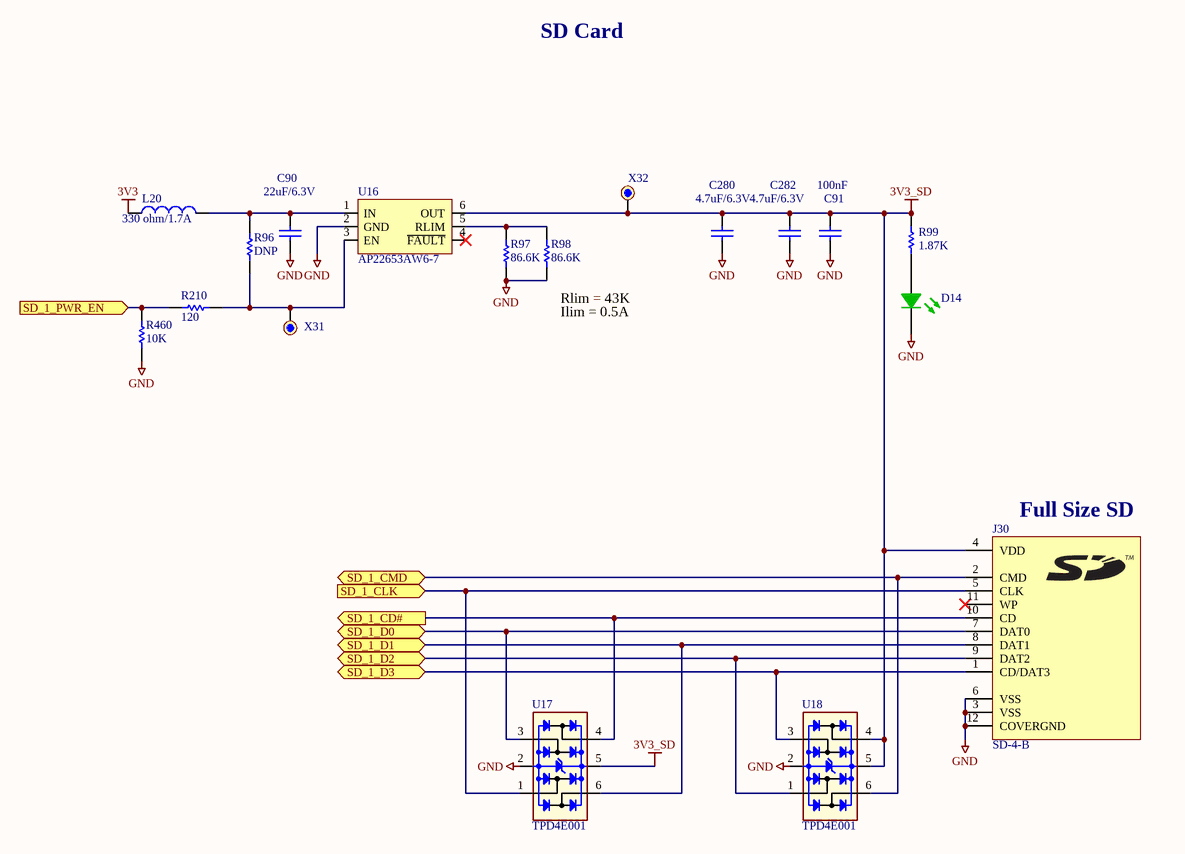
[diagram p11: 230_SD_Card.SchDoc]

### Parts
C90  22uF/6.3V  [C0402_CAPC1005L]
C91  100nF  [C0402_CAPC1005L]
C280  value 4.7uF/6.3V  [C0402_CAPC1005L]  (hidden comment: 0354-Cap-0402-4.7uF/6.3V)
C282  value 4.7uF/6.3V  [C0402_CAPC1005L]  (hidden comment: 0354-Cap-0402-4.7uF/6.3V)
D14  Status  [LED-SMT-0603_APT1608CGCK]  (value not drawn)
J30  SD-4-B  [SD-4-B]
L20  value 330 ohm/1.7A  [C/0603]  (hidden comment: 0405-Fer-0603-330ohm/1.7A)
R96  value DNP  [R/0603]  (hidden comment: 0000-Res-0603-DNP)
R97  value 86.6K  [R0402_RESC1005L]  (hidden comment: 1539-Res-0402-86.6k)
R98  value 86.6K  [R0402_RESC1005L]  (hidden comment: 1539-Res-0402-86.6k)
R99  value 1.87K  [R0402_RESC1005L]  (hidden comment: 1536-Res-0402-1.87K)
R210  value 120  [R0402_RESC1005L]  (hidden comment: 1552-Res-0402-120)
R460  value 10K  [R0402_RESC1005L]  (hidden comment: 1572-Res-0402-10K)
U16  AP22653AW6-7  [sot23-6]
U17  TPD4E001  [SOT23-6]
U18  TPD4E001  [SOT23-6]
X31  000-TestPoint  [TestPoint_1]  (value not drawn)
X32  000-TestPoint  [TestPoint_1]  (value not drawn)

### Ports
SD_1_CD# (out), SD_1_CLK (in), SD_1_CMD (bidir), SD_1_D0 (bidir), SD_1_D1 (bidir), SD_1_D2 (bidir), SD_1_D3 (bidir), SD_1_PWR_EN (in)

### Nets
3V3: L20.1
3V3_SD: C91.2 C280.2 C282.2 J30.4(VDD) R99.2 U16.6(OUT) U17.5 U18.4 U18.5 X32.1
GND: C90.1 C91.1 C280.1 C282.1 D14.2(K) J30.3(VSS) J30.6(VSS) J30.12(COVERGND) R97.1 R98.1 R460.2 U16.2(GND) U17.2 U18.2
SD_1_CD#: J30.10(CD) U17.4 ; port SD_1_CD#
SD_1_CLK: J30.5(CLK) U17.1 ; port SD_1_CLK
SD_1_CMD: J30.2(CMD) U18.6 ; port SD_1_CMD
SD_1_D0: J30.7(DAT0) U17.3 ; port SD_1_D0
SD_1_D1: J30.8(DAT1) U17.6 ; port SD_1_D1
SD_1_D2: J30.9(DAT2) U18.1 ; port SD_1_D2
SD_1_D3: J30.1(CD/DAT3) U18.3 ; port SD_1_D3
SD_1_PWR_EN: R210.2 R460.1 ; port SD_1_PWR_EN
NetC90_2: C90.2 L20.2 R96.1 U16.1(IN)
NetD14_1: D14.1(A) R99.1
NetR96_2: R96.2 R210.1 U16.3(EN) X31.1
NetR97_2: R97.2 R98.2 U16.5(RLIM)

Not connected (* = marked no-connect by the designer): J30 11(WP)*; U16 4(~{FAULT})*

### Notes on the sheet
- SD Card
- (near R98) Rlim = 43K
- (near R98) Ilim = 0.5A
- (near J30) Full Size SD

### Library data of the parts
C90 = 2404-Cap-0402-22uF/6.3V: as C39 on sheet 220_Debug
C91 = 1566-Cap-0402-100nF/50V: as C65-C70 on sheet 210_Translators
C280 C282 = 0354-Cap-0402-4.7uF/6.3V: (-55 to 85 DegC) CAP CER 4.7UF 6.3V 20% X5R 0402; MfrNo: GRM155R60J475ME87D; Mfr: Murata Electronics North America; PN: 354; Alt: 1276-1483-1-ND; Alt2: 490-5915-1-ND
D14 = 0333-LED Green 0603: as D11 on sheet 220_Debug
J30 = 2184-Conn-SD: (-40 to 85 DegC) CONN SD CARD PUSH-PULL R/A, OPEN; Mfr: Same Sky; PN: 2184
L20 = 0405-Fer-0603-330ohm/1.7A: as L13 on sheet 220_Debug
R96 = 0000-Res-0603-DNP: RES 0603
R97 R98 = 1539-Res-0402-86.6k: as R85 on sheet 220_Debug
R99 = 1536-Res-0402-1.87K: (-55 to 155 DegC AEC) RES 1.87K OHM 1% 1/16W 100ppm 0402; MfrNo: RMCF0402FT1K87; Mfr: Stackpole Electronics; Alt: AC0402FR-071K87L,RK73H1ETTP1871F,ERJ-2RKF1871X; PN: 1536
R210 = 1552-Res-0402-120: as R220 on sheet 310_USB3
R460 = 1572-Res-0402-10K: as R108 on sheet 300_USB1_OTG
U16 = 1475-AP22653: as U28 on sheet 310_USB3
U17 U18 = 0740-TPD4E001: as U12 on sheet 220_Debug
X31 X32 = 000-TestPoint: as X29 on sheet 220_Debug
